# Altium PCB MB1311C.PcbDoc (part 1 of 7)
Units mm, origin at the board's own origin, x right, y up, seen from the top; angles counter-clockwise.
Board outline 100.03 x 67.03 mm, 6 copper layers (Top Layer, layer2, layer3, layer4, layer5, Bottom Layer), stack 1.208 mm thick; 366 components, 356 nets, 1582 pads, 964 vias.
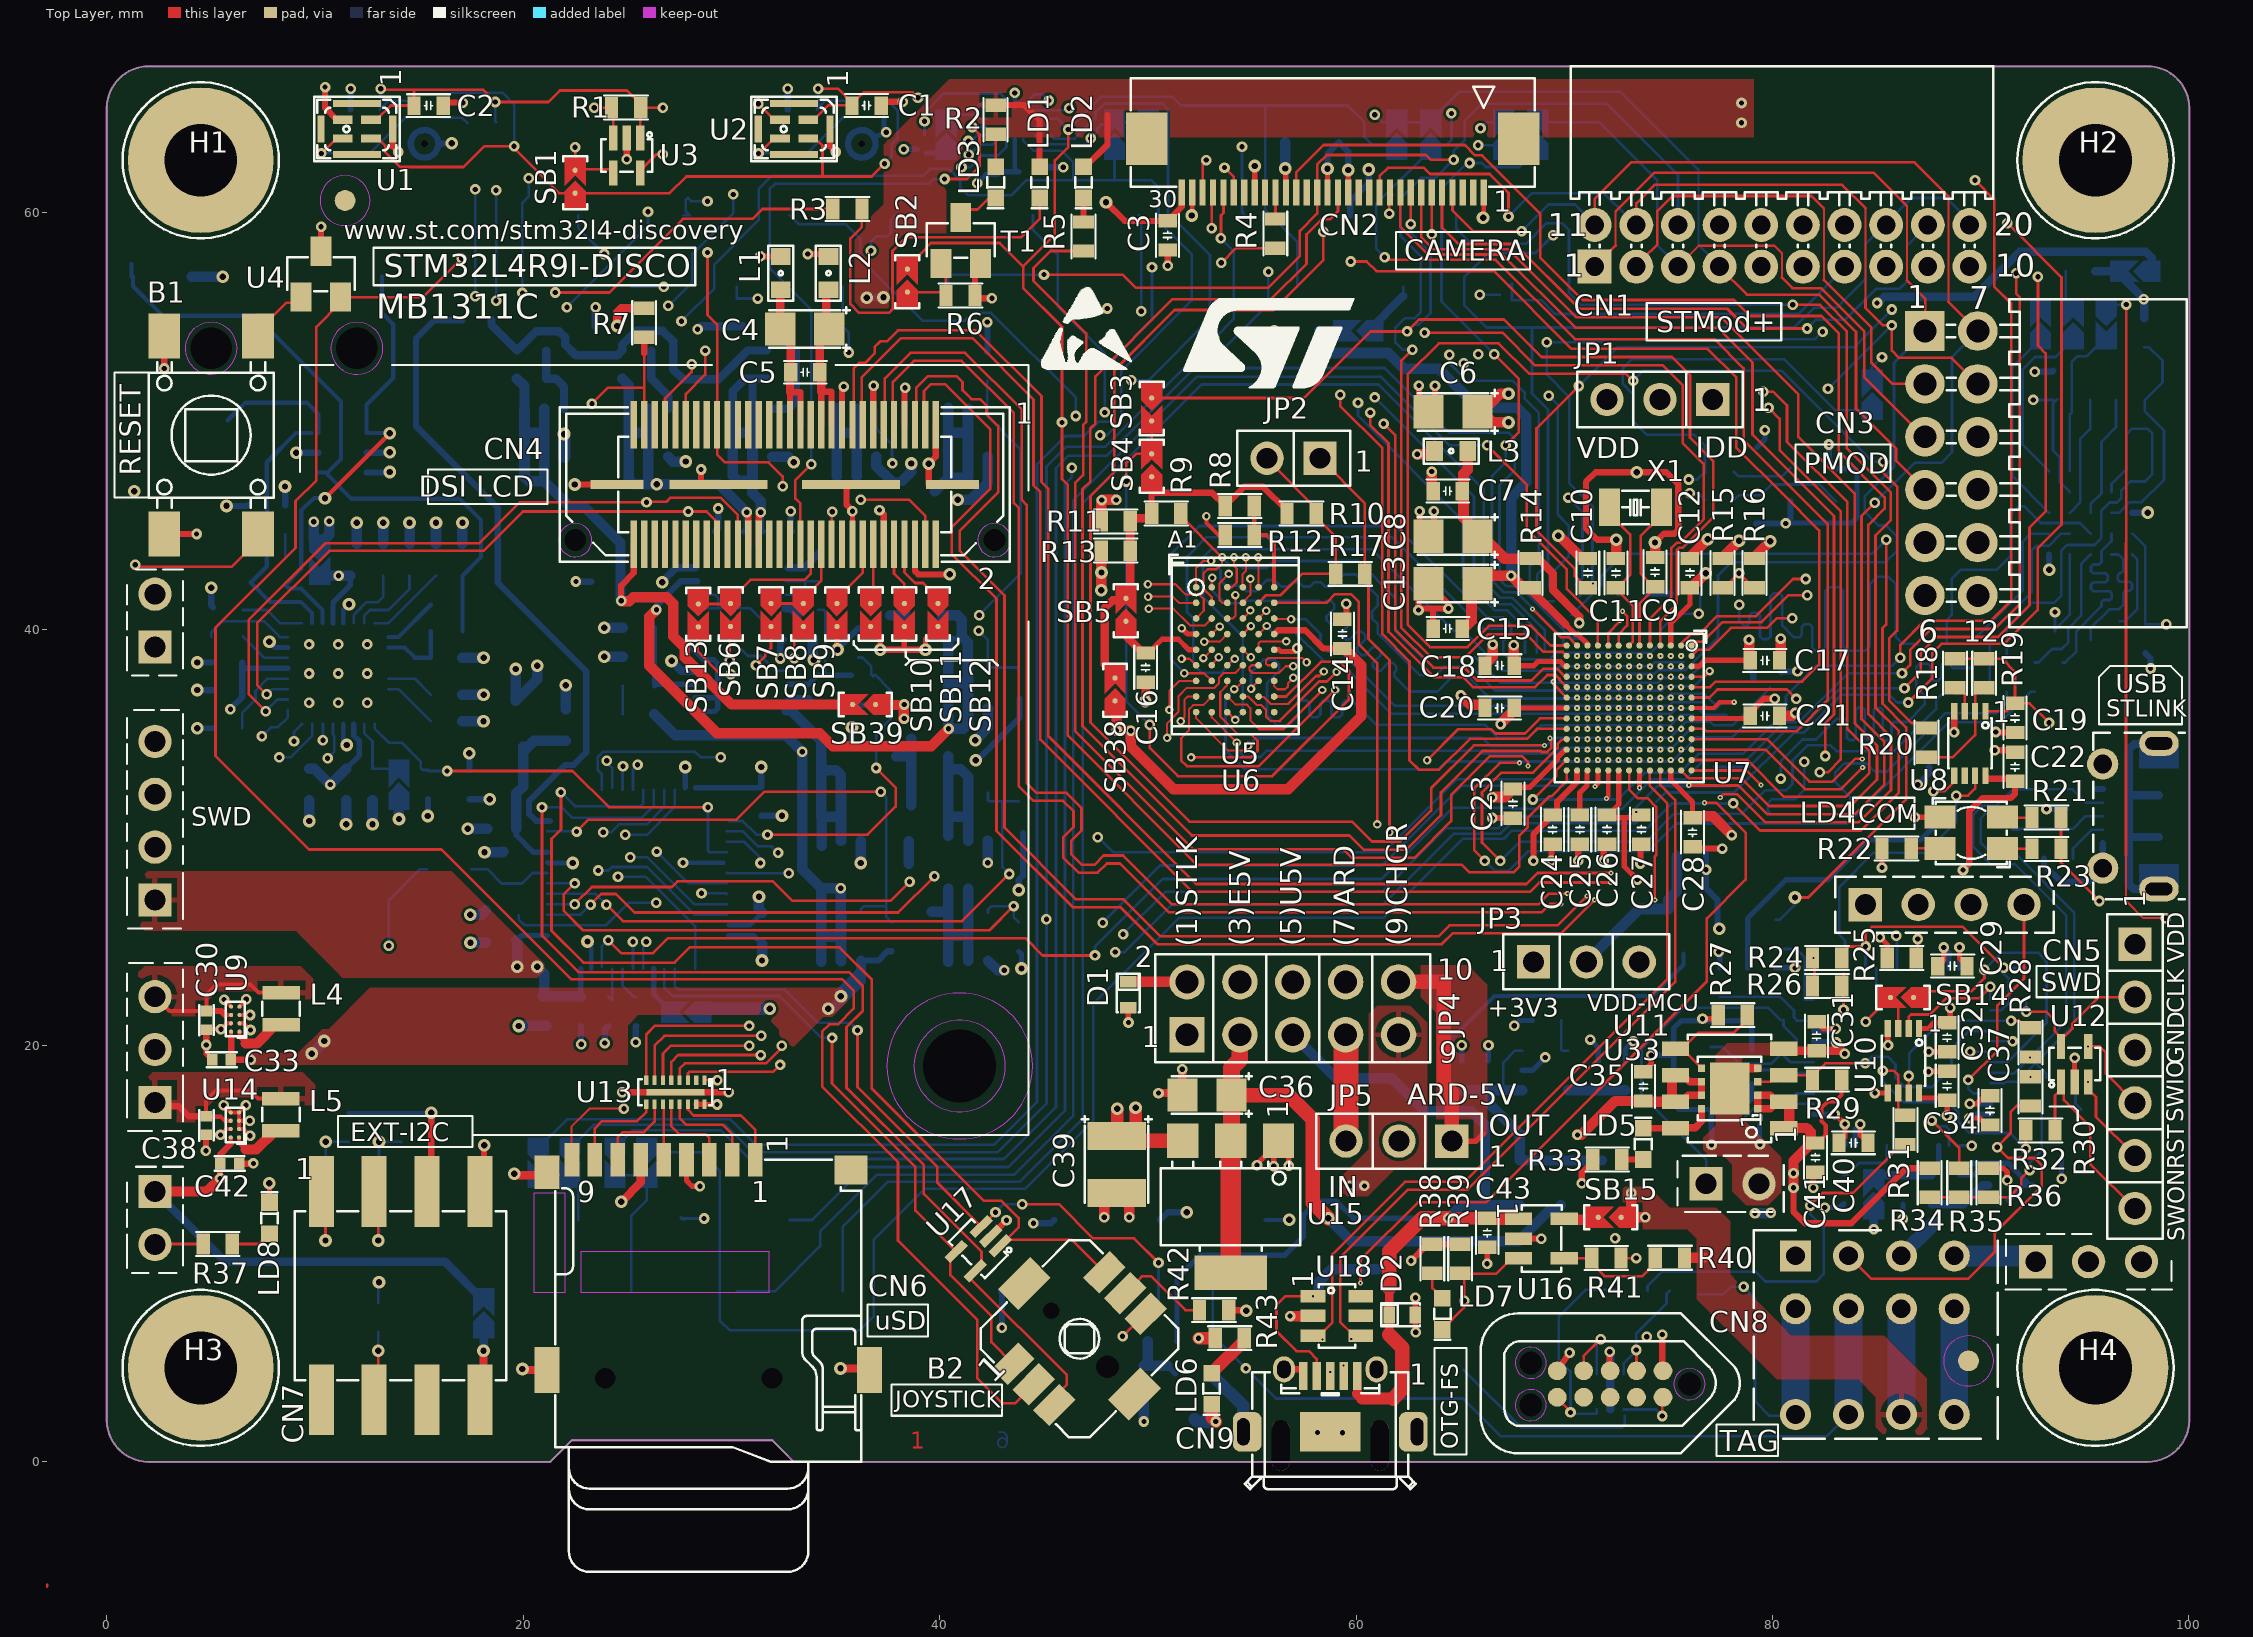
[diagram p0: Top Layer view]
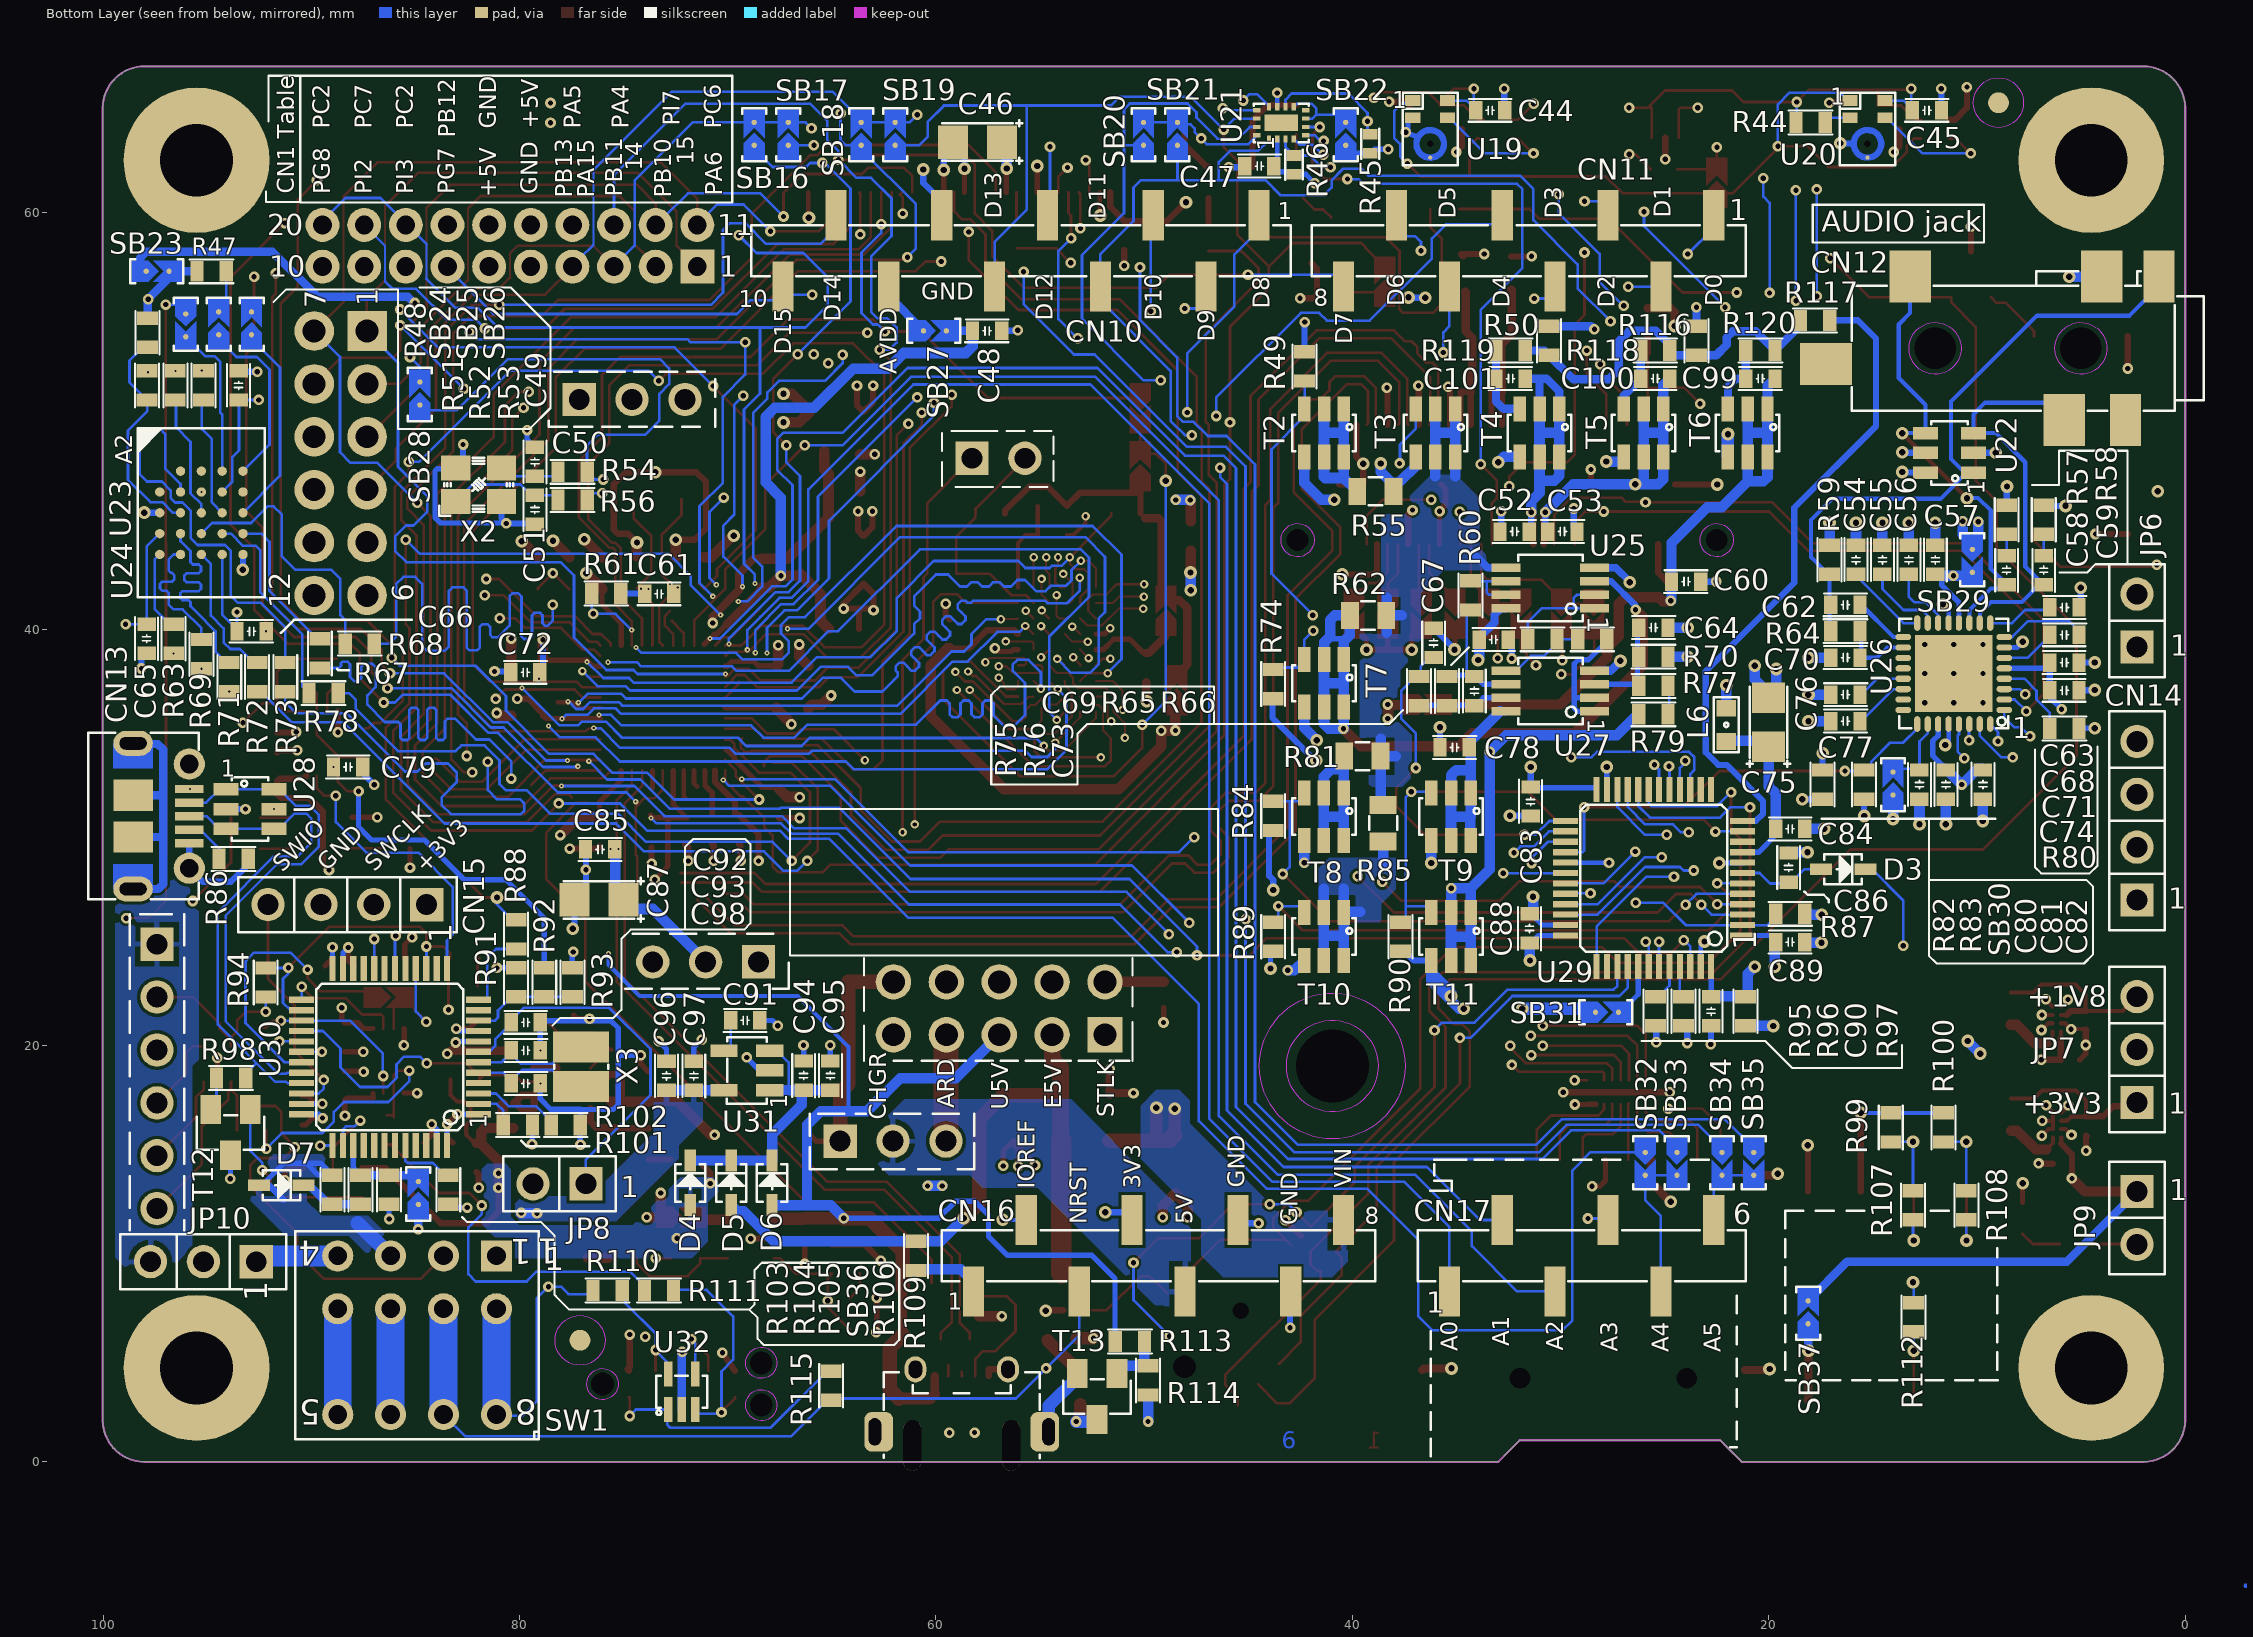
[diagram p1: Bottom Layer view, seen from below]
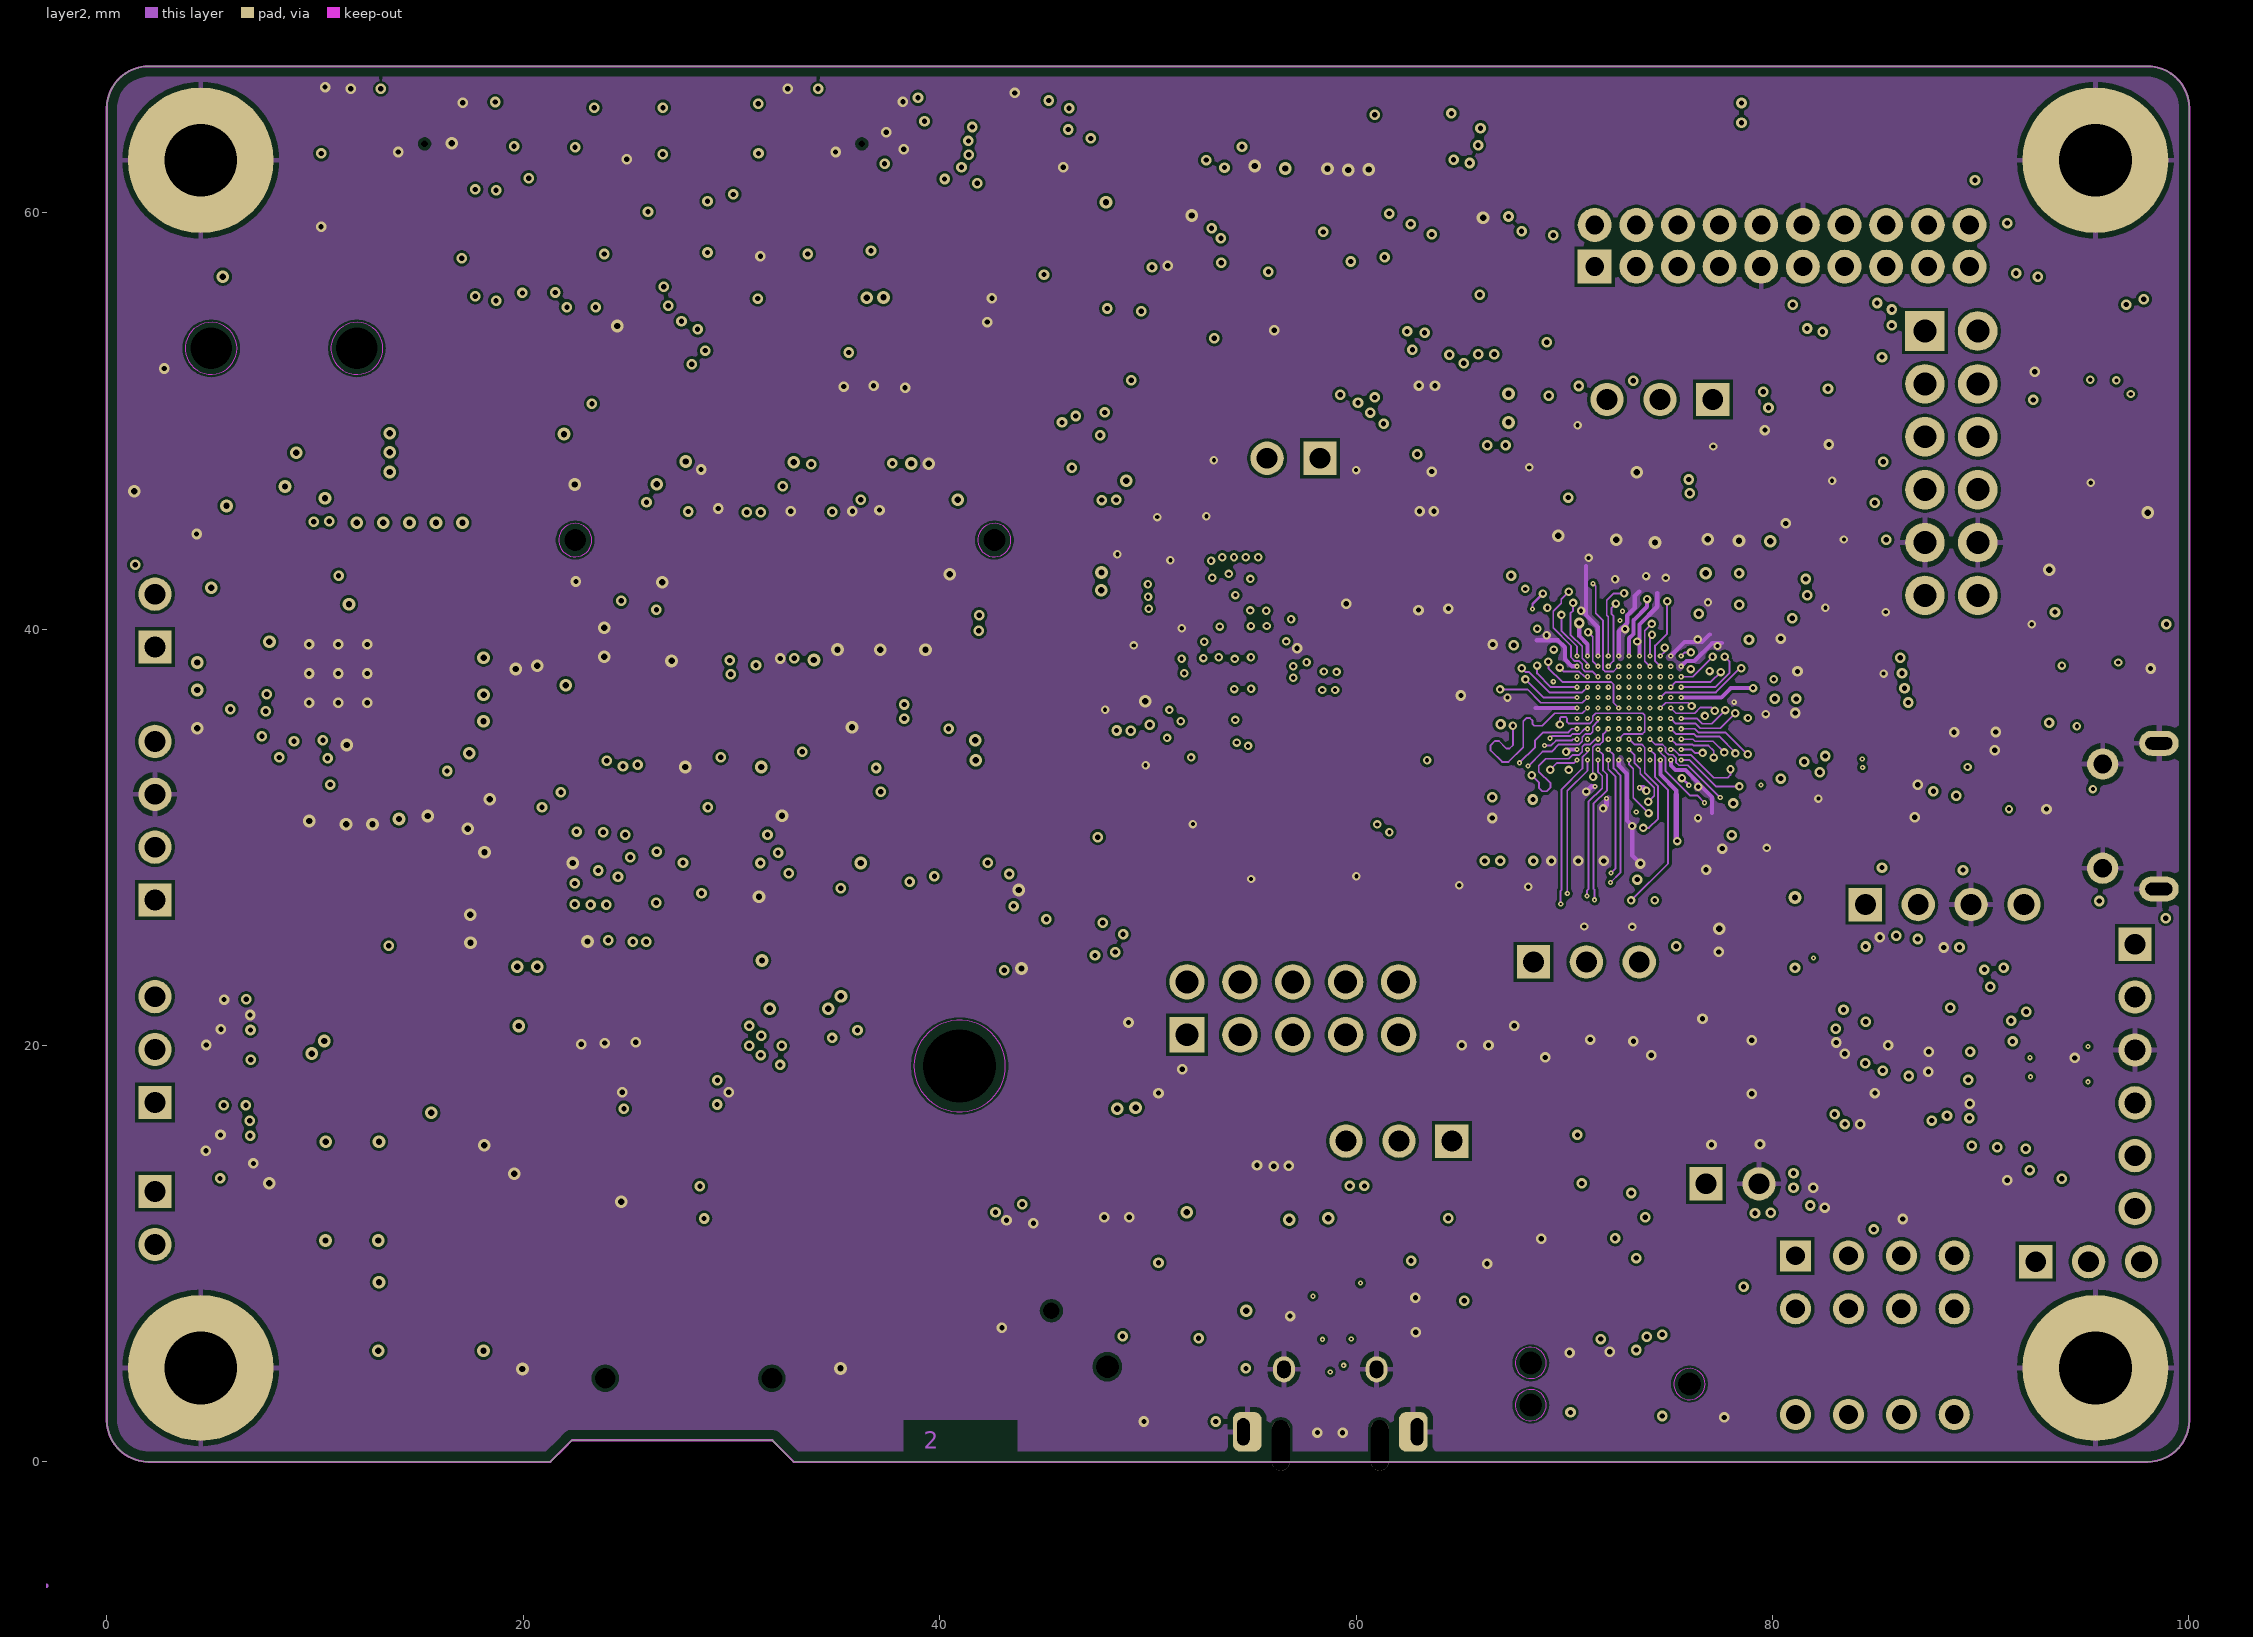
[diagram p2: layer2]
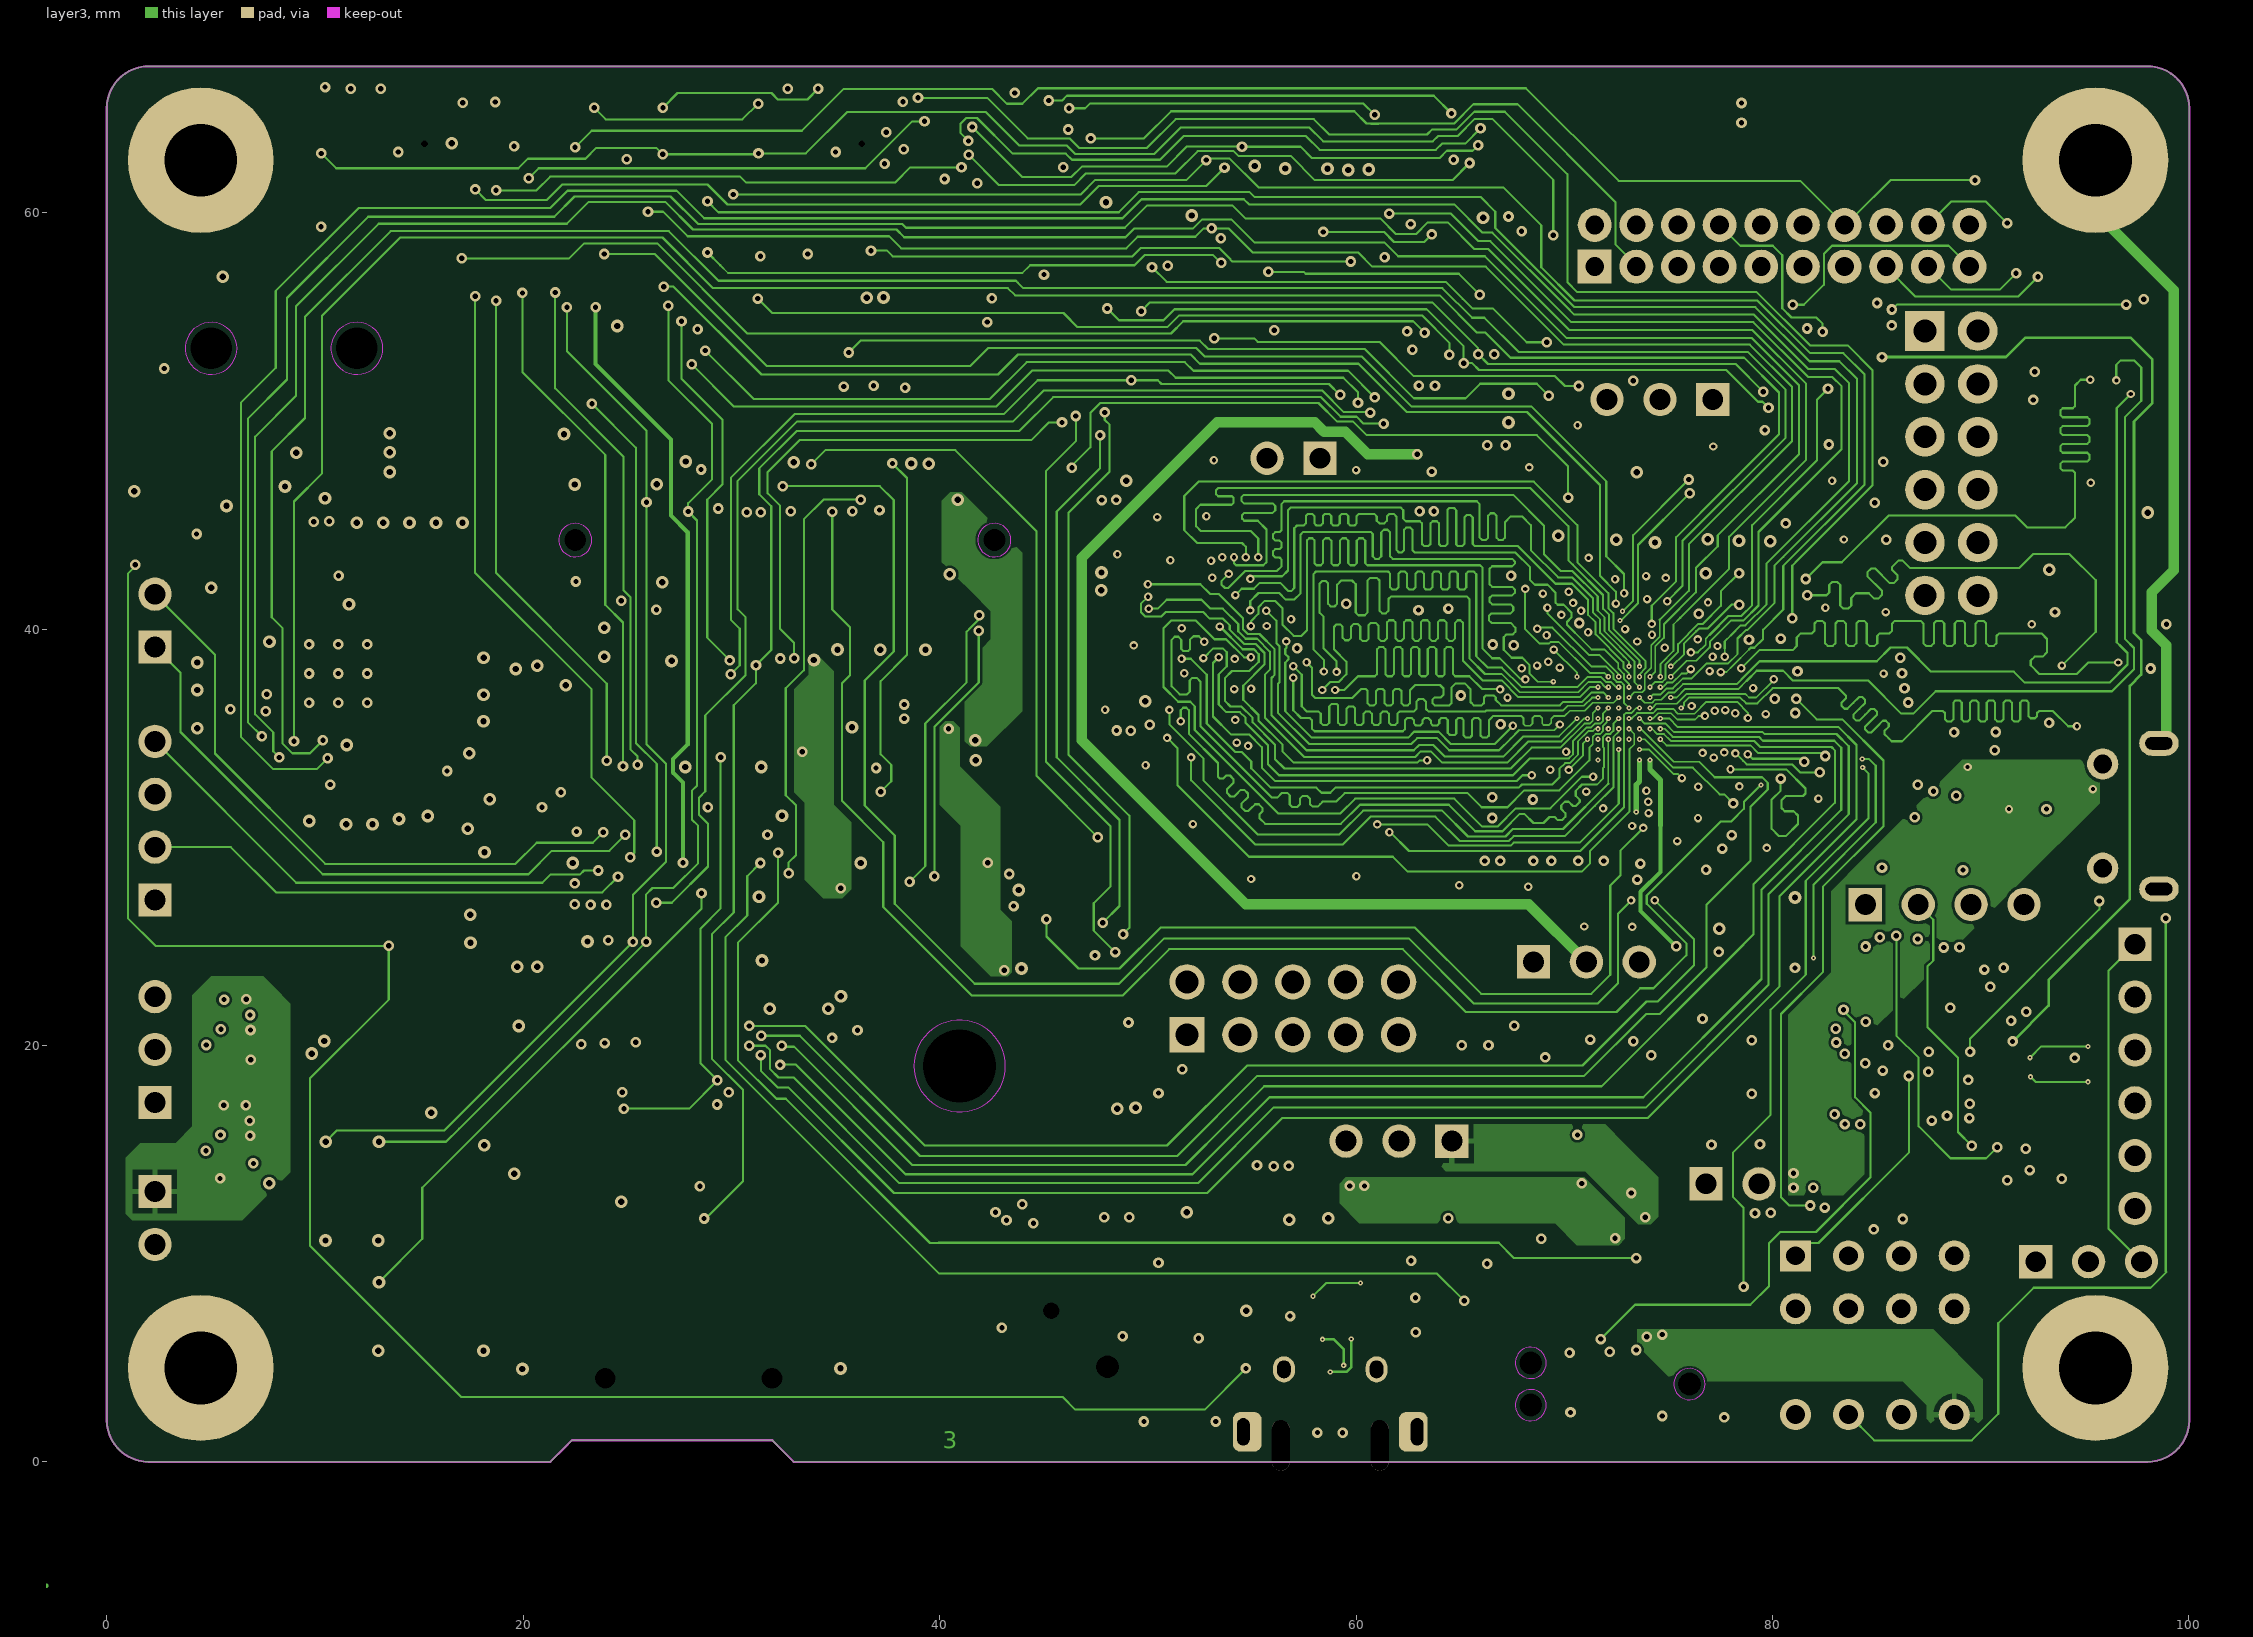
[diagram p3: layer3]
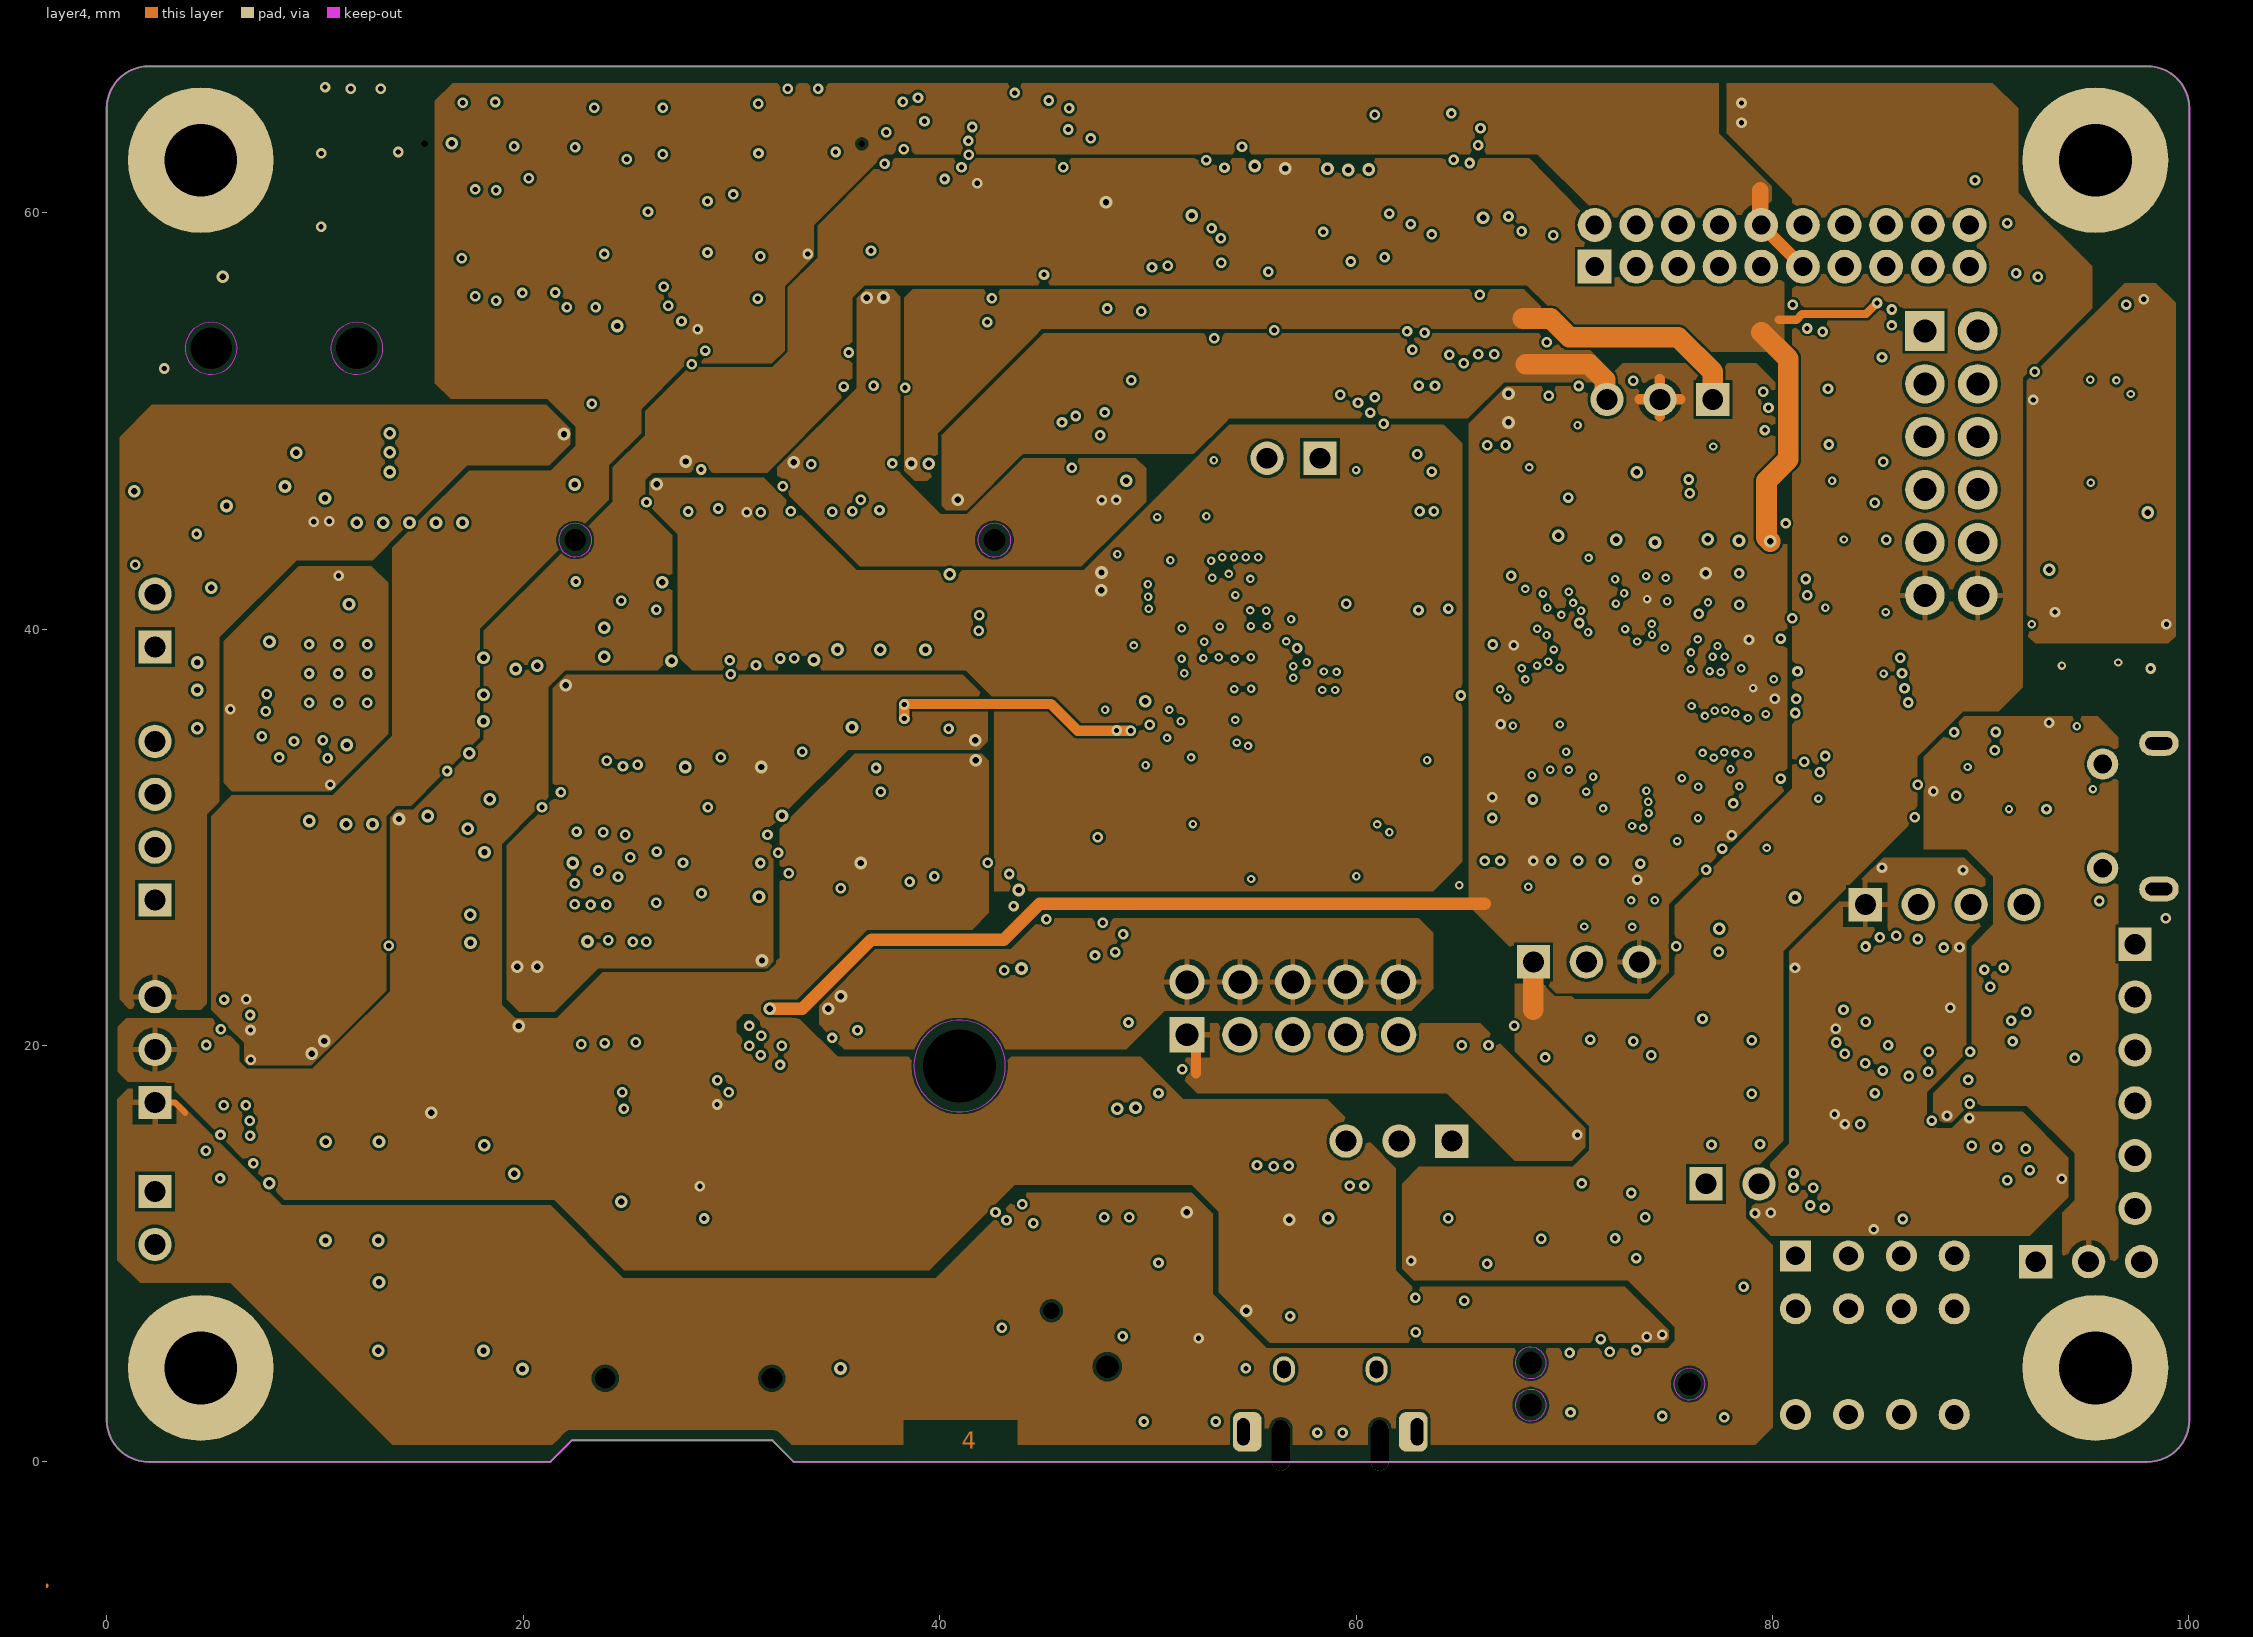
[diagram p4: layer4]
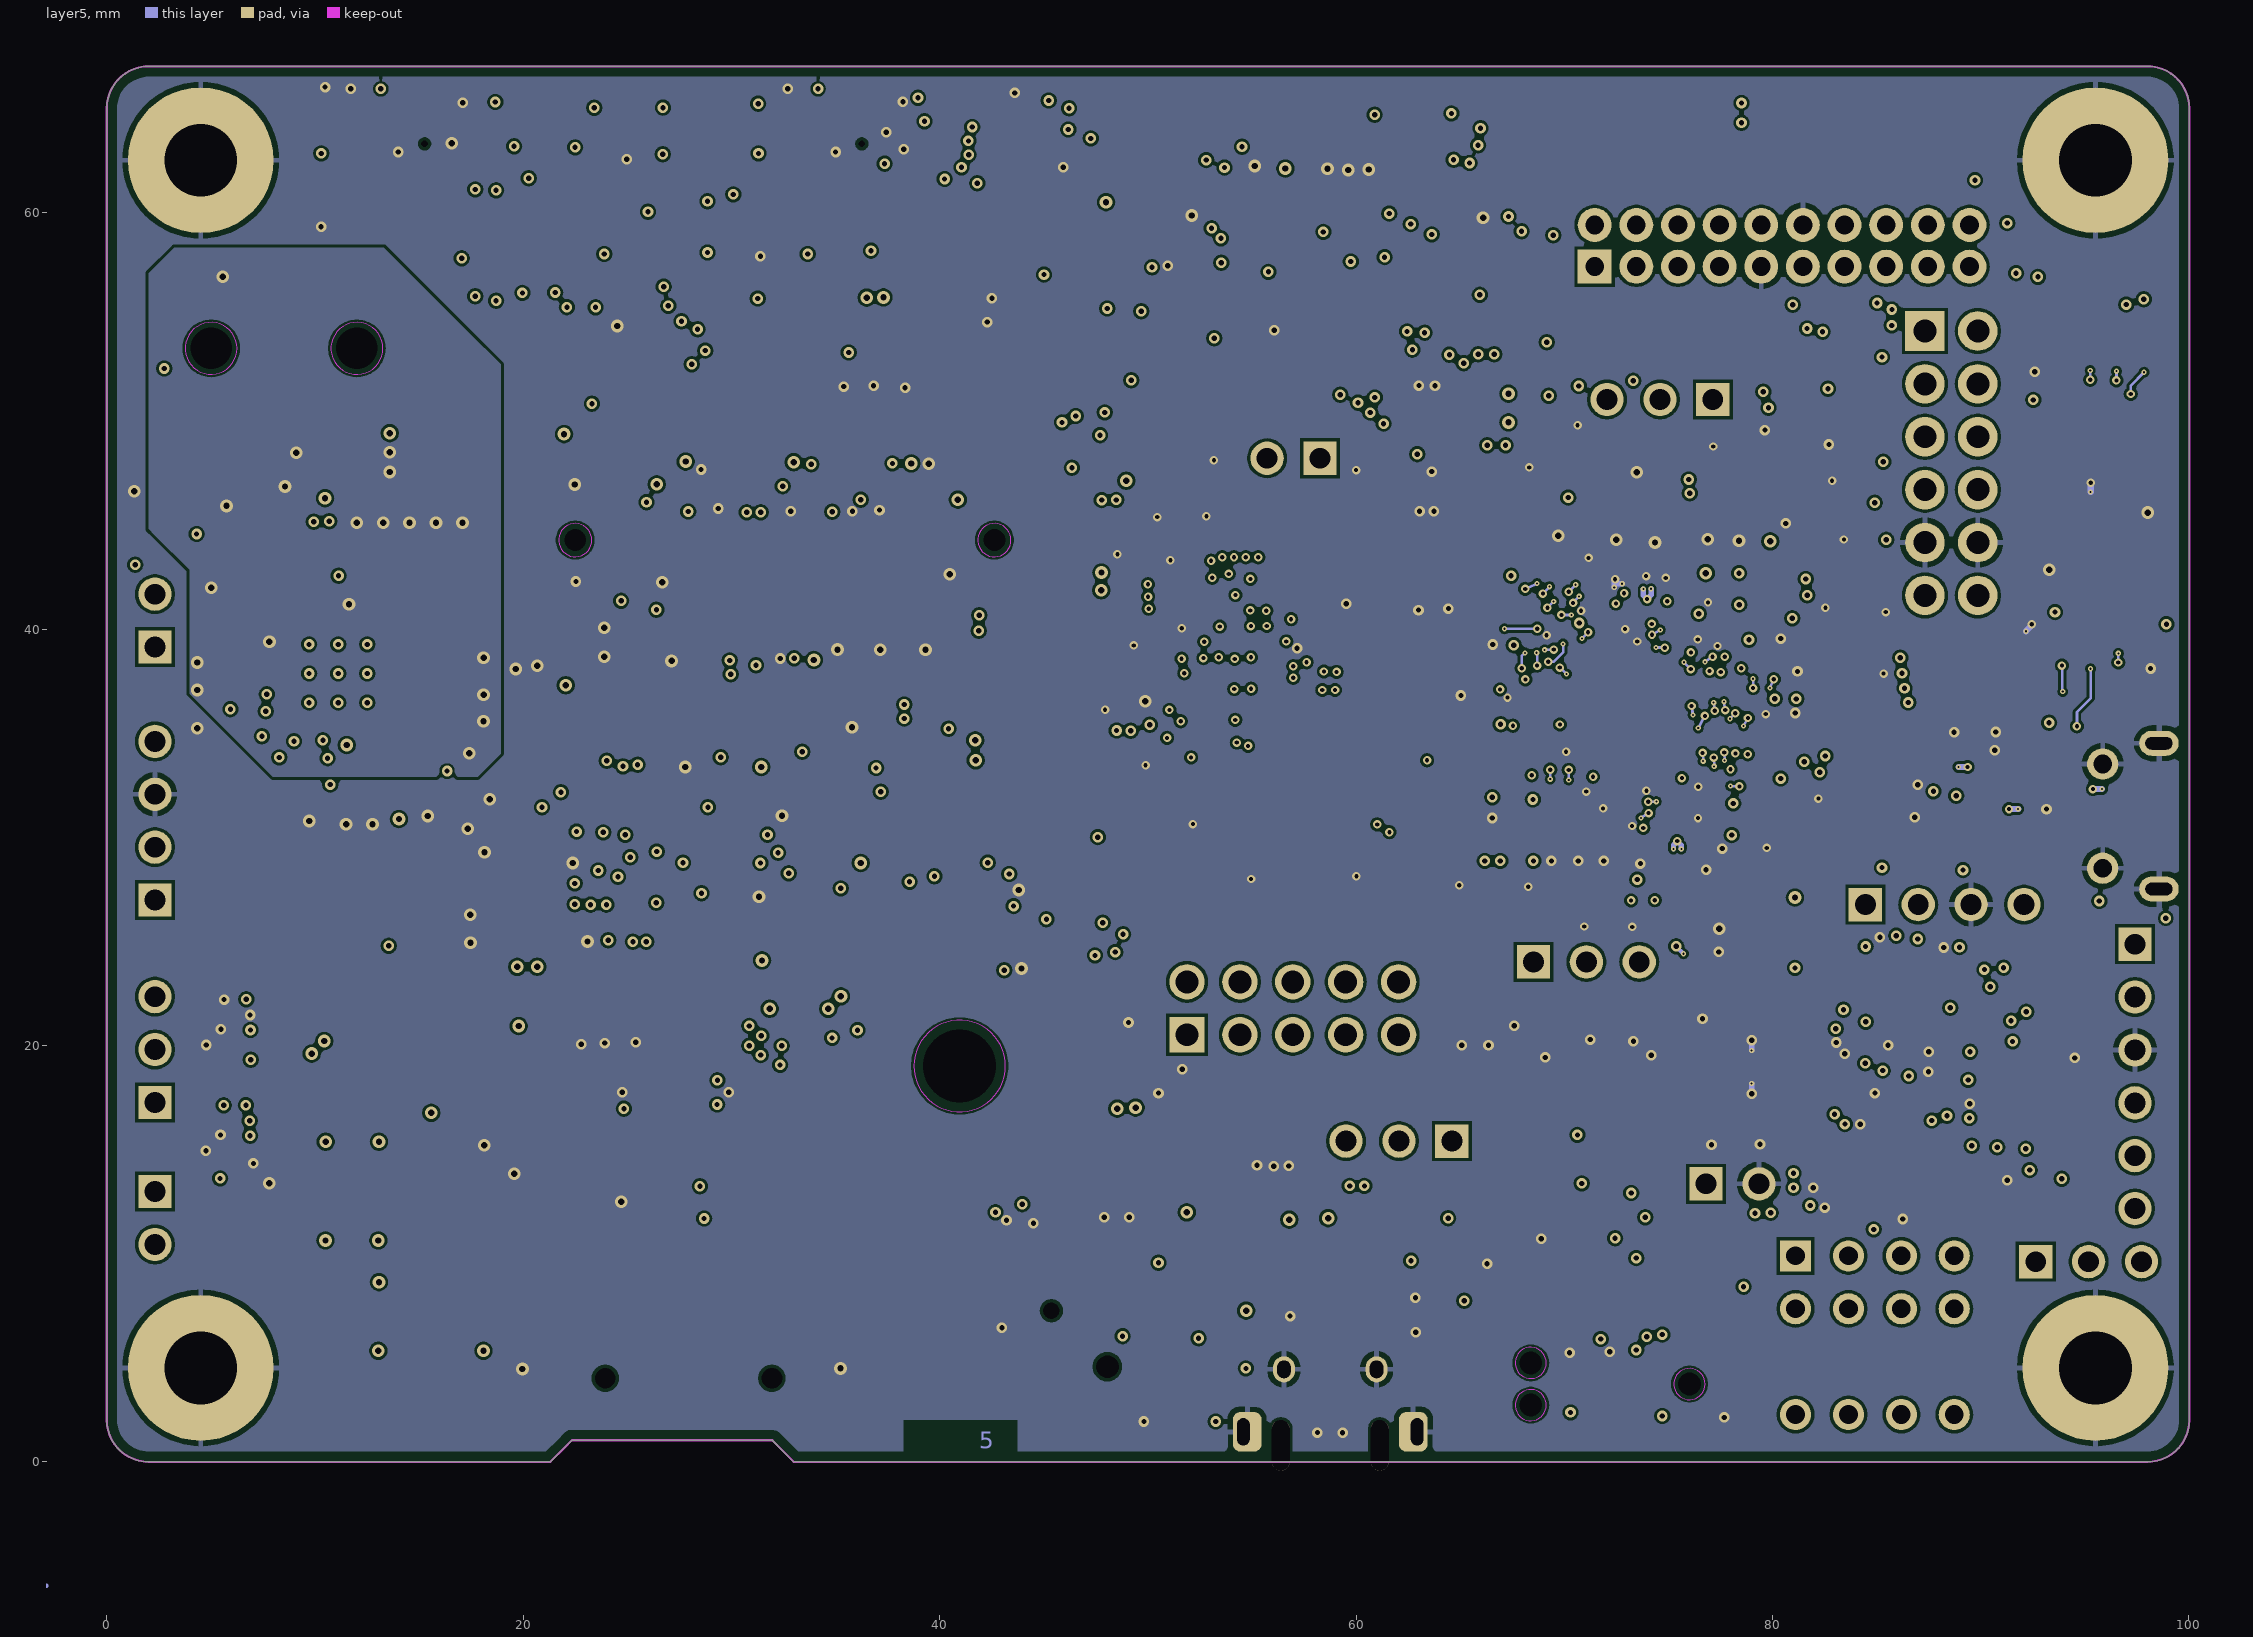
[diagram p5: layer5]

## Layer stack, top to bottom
Top Solder: solder mask 0.01, Solder Resist, Dk 3.5
Top Layer: signal copper 0.042
Dielectric 1: core 0.072, FR-4, Dk 4.2
layer2: signal copper 0.035
Dielectric 2: prepreg 0.0785, FR-4, Dk 4.3
layer3: signal copper 0.0175
Dielectric 3: core 0.71, FR-4, Dk 4.3
layer4: signal copper 0.0175
Dielectric 4: prepreg 0.087, FR-4, Dk 4.3
layer5: signal copper 0.035
Dielectric 5: core 0.072, FR-4, Dk 4.2
Bottom Layer: signal copper 0.042
Bottom Solder: solder mask 0.01, Solder Resist, Dk 3.5

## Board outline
2.013,0 21.3,0 22.013,0.713 22.338,1.038 31.963,1.038 32.988,0 33.263,0 95.676,0 98.013,0 ccw(c98.013,2.013) 100.026,2.013 100.026,65.013 ccw(c98.013,65.013) 98.013,67.026 2.013,67.026 ccw(c2.013,65.013) 0,65.013 0,2.013 ccw(c2.013,2.013)

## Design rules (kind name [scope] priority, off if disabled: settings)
AssemblyTestPointUsage AssemblyTestPointUsage_1 [All] p1:
AssemblyTestPointUsage [All] p2:
AssemblyTestpoint AssemblyTestpoint_1 [All] p1: testpointundercomponent=TRUE minsize=1.016 maxsize=2.54 preferedsize=1.524 minholesize=0 maxholesize=1.016 preferedholesize=0.813 testpointgrid=0.025 usegrid=TRUE gridtolerance=0 allowsidetop=TRUE allowsidebottom=TRUE
AssemblyTestpoint [All] p2: testpointundercomponent=TRUE minsize=1.016 maxsize=2.54 preferedsize=1.524 minholesize=0 maxholesize=1.016 preferedholesize=0.813 testpointgrid=0.025 usegrid=TRUE gridtolerance=0 allowsidetop=TRUE allowsidebottom=TRUE
BoardOutlineClearance [All] p1: gap=0.5 ignorepadtopadclearanceinfootprint=FALSE
Clearance [All] p1: gap=0.127 ignorepadtopadclearanceinfootprint=FALSE except(0: Arc-Region Arc-Hole Track-Region Track-Hole SMDPad-Region SMDPad-Hole THPad-Region THPad-Hole Via-Region Via-Hole Fill-Region Fill-Hole Poly-Region Poly-Hole Region-Region Region-Hole Text-Hole; 0.078: Track-Via; 0.09: Track-Track; 0.12: Arc-Arc Arc-Track Arc-SMDPad Arc-THPad Arc-Via Arc-Poly Track-SMDPad Track-THPad SMDPad-SMDPad SMDPad-THPad SMDPad-Via THPad-Via; 0.15: THPad-Poly Fill-Poly Poly-Poly)
ComponentClearance ComponentClearance_DI [InComponent('U11') vs InComponent('U33')] p1: gap=-10 collisioncheckmode=3 verticalgap=-10 showdistances=TRUE
ComponentClearance ComponentClearance_1 [All] p2: gap=0.254 collisioncheckmode=3 verticalgap=0.254 showdistances=FALSE
ComponentClearance [All] p3: gap=0.025 collisioncheckmode=3 verticalgap=2540 showdistances=FALSE
DiffPairsRouting PAIR__DSI [InDifferentialPairClass('DSI')] p1: maxlimit=0.254 minlimit=0.15 mostfreqgap=0.254 toplayer_minwidth=0.088 toplayer_maxwidth=0.127 toplayer_prefwidth=0.127 midlayer1_prefgap=0.15 midlayer1_minwidth=0.088 midlayer1_maxwidth=0.127 midlayer1_prefwidth=0.088 midlayer2_minwidth=0.088 midlayer2_maxwidth=0.127 midlayer2_prefwidth=0.127 midlayer3_minwidth=0.088 midlayer3_maxwidth=0.127 midlayer3_prefwidth=0.127 midlayer4_minwidth=0.088 midlayer4_maxwidth=0.127 midlayer4_prefwidth=0.127 bottomlayer_minwidth=0.088 bottomlayer_maxwidth=0.127 bottomlayer_prefwidth=0.127 maxuncoupledlength=12.7
DiffPairsRouting PAIR__USB [InDifferentialPairClass('USB')] p2: maxlimit=0.254 minlimit=0.254 mostfreqgap=0.254 toplayer_minwidth=0.122 toplayer_maxwidth=0.122 toplayer_prefwidth=0.122 midlayer1_minwidth=0.122 midlayer1_maxwidth=0.122 midlayer1_prefwidth=0.122 midlayer2_minwidth=0.122 midlayer2_maxwidth=0.122 midlayer2_prefwidth=0.122 midlayer3_minwidth=0.122 midlayer3_maxwidth=0.122 midlayer3_prefwidth=0.122 midlayer4_minwidth=0.122 midlayer4_maxwidth=0.122 midlayer4_prefwidth=0.122 bottomlayer_minwidth=0.122 bottomlayer_maxwidth=0.122 bottomlayer_prefwidth=0.122 maxuncoupledlength=12.7
FabricationTestPointUsage FabricationTestPointUsage_1 [All] p1: valid=0 allowmultiple=FALSE
FabricationTestPointUsage [All] p2: valid=0 allowmultiple=FALSE
FabricationTestpoint FabricationTestpoint_1 [All] p1: side=3 testpointundercomponent=TRUE minsize=1.016 maxsize=2.54 preferedsize=1.524 minholesize=0 maxholesize=1.016 preferedholesize=0.813 testpointgrid=0.025 allowsidetop=TRUE allowsidebottom=TRUE usegrid=TRUE gridtolerance=0
FabricationTestpoint [All] p2: side=3 testpointundercomponent=TRUE minsize=1.016 maxsize=2.54 preferedsize=1.524 minholesize=0 maxholesize=1.016 preferedholesize=0.813 testpointgrid=0.025 allowsidetop=TRUE allowsidebottom=TRUE usegrid=TRUE gridtolerance=0
FanoutControl Fanout_Default_1 [All] p1: bgadir=Out bgaviamode=Centered fanoutstyle=Auto fanoutdirection=Alternating viagrid=0.025 // Fanout_Default (Default Rule)
FanoutControl Fanout_Small_1 [(CompPinCount < 5)] p2: bgadir=Out bgaviamode=Centered fanoutstyle=Auto fanoutdirection=OutThenIn viagrid=0.025 // Fanout_Small (Default Rule)
FanoutControl Fanout_SOIC_1 [IsSOIC] p3: bgadir=Out bgaviamode=Centered fanoutstyle=Auto fanoutdirection=Alternating viagrid=0.025 // Fanout_SOIC (Default Rule)
FanoutControl Fanout_LCC_1 [IsLCC] p4: bgadir=Out bgaviamode=Centered fanoutstyle=Auto fanoutdirection=Alternating viagrid=0.025 // Fanout_LCC (Default Rule)
FanoutControl Fanout_BGA_1 [IsBGA] p5: bgadir=Out bgaviamode=Centered fanoutstyle=Auto fanoutdirection=Alternating viagrid=0.025 // Fanout_BGA (Default Rule)
FanoutControl Fanout_BGA [IsBGA] p6: bgadir=Out bgaviamode=Centered fanoutstyle=Auto fanoutdirection=Alternating viagrid=0.025 // Fanout_BGA (Default Rule)
FanoutControl Fanout_LCC [IsLCC] p7: bgadir=Out bgaviamode=Centered fanoutstyle=Auto fanoutdirection=Alternating viagrid=0.025 // Fanout_LCC (Default Rule)
FanoutControl Fanout_SOIC [IsSOIC] p8: bgadir=Out bgaviamode=Centered fanoutstyle=Auto fanoutdirection=Alternating viagrid=0.025 // Fanout_SOIC (Default Rule)
FanoutControl Fanout_Small [(CompPinCount < 5)] p9: bgadir=Out bgaviamode=Centered fanoutstyle=Auto fanoutdirection=OutThenIn viagrid=0.025 // Fanout_Small (Default Rule)
FanoutControl Fanout_Default [All] p10: bgadir=Out bgaviamode=Centered fanoutstyle=Auto fanoutdirection=Alternating viagrid=0.025 // Fanout_Default (Default Rule)
Height Height_1 [All] p1: minheight=0 maxheight=25.4 prefheight=12.7
Height [All] p2: minheight=0 maxheight=25.4 prefheight=12.7
HoleSize HoleSize_1 [All] p1: absolutevalues=TRUE maxlimit=2.54 minlimit=0.025 maxpercent=80.000 minpercent=20.000
HoleSize [All] p2: absolutevalues=TRUE maxlimit=10 minlimit=0.15 maxpercent=80.000 minpercent=20.000
HoleToHoleClearance HoleToHoleClearance_1 [All] p1: gap=0.254 allowstackedmicrovias=TRUE
HoleToHoleClearance [All] p2: gap=0.254 allowstackedmicrovias=TRUE
LayerPairs LayerPairs_1 [All] p1: enforce=TRUE
LayerPairs [All] p2: enforce=TRUE
MatchedLengths psram_adr_ctrl [InNetClass('PSRAM_adr_ctrl')] p1: tolerance=5.1 checknetsindiffpair=FALSE checkdiffpairvsdiffpair=TRUE checkxsignals=TRUE checkothers=TRUE
MatchedLengths octospim [InxSignalClass('OCTOSPIM')] p2: tolerance=5.1 checknetsindiffpair=FALSE checkdiffpairvsdiffpair=TRUE checkxsignals=TRUE checkothers=TRUE
MatchedLengths Psram_data [InNetClass('PSRAM_data')] p3: tolerance=5.1 checknetsindiffpair=FALSE checkdiffpairvsdiffpair=TRUE checkxsignals=TRUE checkothers=TRUE
MinimumSolderMaskSliver MinimumSolderMaskSliver_1 [All] p1: minsoldermaskwidth=0.254
MinimumSolderMaskSliver [All] p2: minsoldermaskwidth=0.254
NetAntennae NetAntennae_1 [All] p1: netantennaetolerance=0
NetAntennae [All] p2: netantennaetolerance=0
PasteMaskExpansion PasteMaskExpansion_1 [All] p1: expansion=0
PasteMaskExpansion [All] p2: expansion=0
PermittedLayers [All] p1: toplayerpermitted=TRUE bottomlayerpermitted=TRUE
PlaneClearance PlaneClearance_1 [All] p1: clearance=0.508
PlaneClearance [All] p2: clearance=0.508
PlaneConnect PlaneConnect_1 [All] p1: planeconnectstyle=Direct reliefexpansion=0.508 reliefentries=4 reliefconductorwidth=0.254 reliefairgap=0.254
PlaneConnect [All] p2: planeconnectstyle=Relief reliefexpansion=0.508 reliefentries=4 reliefconductorwidth=0.254 reliefairgap=0.254
PolygonConnect PolygonConnect_6 [All vs IsNamedPolygon('GND_L01_P780')] p1: connectstyle=Direct reliefconductorwidth=0.254 reliefentries=4 polygonreliefangle="90 Angle" airgapwidth=0.254
PolygonConnect PolygonConnect_5 [All vs IsNamedPolygon('GND_L01_P780')] p2: thpad.connectstyle=Relief thpad.reliefconductorwidth=0.35 thpad.reliefentries=4 thpad.polygonreliefangle="90 Angle" thpad.airgapwidth=0.3 smdpad.connectstyle=Direct smdpad.reliefconductorwidth=0.254 smdpad.reliefentries=4 smdpad.polygonreliefangle="90 Angle" smdpad.airgapwidth=0.254 via.connectstyle=Direct via.reliefconductorwidth=0.254 via.reliefentries=4 via.polygonreliefangle="90 Angle" via.airgapwidth=0.254
PolygonConnect PolygonConnect_4 [All vs IsVia] p3: connectstyle=Direct reliefconductorwidth=0.254 reliefentries=4 polygonreliefangle="90 Angle" airgapwidth=0.254
PolygonConnect PolygonConnect_3 [All vs IsPad] p4: connectstyle=Relief reliefconductorwidth=0.254 reliefentries=4 polygonreliefangle="90 Angle" airgapwidth=0.254
PolygonConnect PolygonConnect_2 [All] p5: connectstyle=Relief reliefconductorwidth=0.254 reliefentries=4 polygonreliefangle="90 Angle" airgapwidth=0.254
PolygonConnect PolygonConnect_VIAS-DIRECT [(ObjectKind = 'Via')] p6: connectstyle=Direct reliefconductorwidth=0.254 reliefentries=4 polygonreliefangle="90 Angle" airgapwidth=0.254
PolygonConnect PolygonConnect_1 [All] p7: connectstyle=Direct reliefconductorwidth=0.254 reliefentries=4 polygonreliefangle="90 Angle" airgapwidth=0.254
PolygonConnect 4_PTH_MECA [(ObjectKind = 'Pad') And (AsMM(HoleDiameter) = 3.5)] p8: connectstyle=Direct reliefconductorwidth=0.254 reliefentries=4 polygonreliefangle="90 Angle" airgapwidth=0.254
PolygonConnect PAD_CMS_NC [(ObjectKind = 'Pad') And (AsMM(HoleDiameter) = 0)] p9: connectstyle=NoConnect reliefconductorwidth=0.254 reliefentries=4 polygonreliefangle="90 Angle" airgapwidth=0.254
PolygonConnect VIAS_DIRECT [(ObjectKind = 'Via')] p10: connectstyle=Direct reliefconductorwidth=0.254 reliefentries=4 polygonreliefangle="90 Angle" airgapwidth=0.254
PolygonConnect [All] p11: connectstyle=Relief reliefconductorwidth=0.3 reliefentries=4 polygonreliefangle="90 Angle" airgapwidth=0.3
RoutingCorners RoutingCorners_1 [All] p1: cornerstyle=45-Degree minsetback=2.54 maxsetback=2.54
RoutingCorners [All] p2: cornerstyle=45-Degree minsetback=2.54 maxsetback=2.54
RoutingTopology RoutingTopology_1 [All] p1: topology=Shortest
RoutingTopology [All] p2: topology=Shortest
RoutingVias thru [InDrillLayerPair('Top Layer - Bottom Layer')] p1: holewidth=0.254 width=0.508 viastyle="Through Hole" minholewidth=0.102 minwidth=0.254 maxholewidth=0.305 maxwidth=0.61 useviatemplates=TRUE viatemplateguid#1={340DC7B5-3F1E-47EE-990D-81B2755D6B04} viatemplateguid#2={247BE16E-88AE-4C41-9598-B4796CDE4816} viatemplateguid#3={E3B873A7-E7F3-4F44-A42C-17ADC36A370E} viatemplatename#1=v41h20m0mx0 viatemplatename#2=v51h25m0mx0 viatemplatename#3=v61h30m0mx0
RoutingVias buried [InDrillLayerPair('layer2 - layer5')] p2: holewidth=0.254 width=0.508 viastyle="Through Hole" minholewidth=0.102 minwidth=0.254 maxholewidth=0.305 maxwidth=0.61 useviatemplates=TRUE viatemplateguid#1={340DC7B5-3F1E-47EE-990D-81B2755D6B04} viatemplateguid#2={247BE16E-88AE-4C41-9598-B4796CDE4816} viatemplatename#1=v41h20m0mx0 viatemplatename#2=v51h25m0mx0
RoutingVias laser12 [InDrillLayerPair('Top Layer - layer2')] p3: holewidth=0.254 width=0.508 viastyle="Through Hole" minholewidth=0.102 minwidth=0.254 maxholewidth=0.305 maxwidth=0.61 useviatemplates=TRUE viatemplateguid#1={9272D162-69AC-415E-8B8A-D644504FA463} viatemplatename#1=v25h10m0
RoutingVias laser23 [InDrillLayerPair('layer2 - layer3')] p4: holewidth=0.254 width=0.508 viastyle="Through Hole" minholewidth=0.102 minwidth=0.254 maxholewidth=0.305 maxwidth=0.61 useviatemplates=TRUE viatemplateguid#1={340DC7B5-3F1E-47EE-990D-81B2755D6B04} viatemplatename#1=v41h20m0mx0
RoutingVias laser13 [InDrillLayerPair('Top Layer - layer3')] p5: holewidth=0.254 width=0.508 viastyle="Through Hole" minholewidth=0.102 minwidth=0.254 maxholewidth=0.305 maxwidth=0.61 useviatemplates=TRUE viatemplateguid#1={9272D162-69AC-415E-8B8A-D644504FA463} viatemplatename#1=v25h10m0
RoutingVias laser56 [InDrillLayerPair('layer5 - Bottom Layer')] p6: holewidth=0.254 width=0.508 viastyle="Through Hole" minholewidth=0.102 minwidth=0.254 maxholewidth=0.305 maxwidth=0.61 useviatemplates=TRUE viatemplateguid#1={323C149F-07D9-473E-B805-4447FED07B1E} viatemplatename#1=v25h10mx0
SilkToBoardRegionClearance SilkToBoardRegionClearance_1 [All] p1:
SilkToBoardRegionClearance [All] p2:
SilkToSilkClearance SilkToSilkClearance_1 [All] p1: silktosilkclearance=0.254
SilkToSilkClearance [All] p2: silktosilkclearance=0.1
SilkToSolderMaskClearance SilkToSolderMaskClearance_1 [IsPad] p1: minsilkscreentomaskgap=0.254 clearancetoexposedcopper=TRUE
SilkToSolderMaskClearance [IsPad] p2: minsilkscreentomaskgap=0.254 clearancetoexposedcopper=TRUE
SolderMaskExpansion SolderMaskExpansion_2 [All] p1: expansion=0.102
SolderMaskExpansion SolderMaskExpansion_1 [Not All] p2: expansion=0.102
SolderMaskExpansion [All] p3: expansion=0.102
UnRoutedNet UnRoutedNet_1 [All] p1:
UnRoutedNet [All] p2:
Width Width_alims [InNetClass('alims')] p1: maxlimit=5 minlimit=0.1 preferedwidth=0.3
Width [All] p2: maxlimit=10 minlimit=0.088 preferedwidth=0.102 toplayer_minwidth=0.102 toplayer_prefwidth=0.127 midlayer3_minwidth=0.102 midlayer4_minwidth=0.102 bottomlayer_minwidth=0.102 bottomlayer_prefwidth=0.127 minimp=50.000000 maximp=50.000000 favimp=50.000000
4 further rules are at their usual default settings.

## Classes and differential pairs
net class alims: 1V8_CODEC 1V8_LCD 3V3_LCD 5V_STL 5V_USB_CHARGER +1V8 +3V3 +3V3_ST_LINK +5V AGND GND
net class PSRAM_data: D0 D1 D2 D3 D4 D5 D6 D7 D8 D9 D10 D11 D12 D13 D14 D15 PSRAM_CLK
net class DCMI_data: DCMI_D0 DCMI_D1 DCMI_D2 DCMI_D3 DCMI_D4 DCMI_D5 DCMI_D6 DCMI_D7
net class PSRAM_adr_ctrl: PSRAM_A0 PSRAM_A1 PSRAM_A2 PSRAM_A3 PSRAM_A4 PSRAM_A5 PSRAM_A6 PSRAM_A7 PSRAM_A8 PSRAM_A9 PSRAM_A10 PSRAM_A11 PSRAM_A12 PSRAM_A13 PSRAM_A14 PSRAM_A15 PSRAM_A16 PSRAM_A17 PSRAM_A18 PSRAM_A19 PSRAM_ADV PSRAM_NBL0 PSRAM_NBL1 PSRAM_NE1 PSRAM_OE PSRAM_WAIT PSRAM_WE
differential pair class DSI: DSI_CK DSI_D0 DSI_D1
differential pair class USB: D STL_USB_D
differential pair D: +D_P -D_N
differential pair USB: +"" -""
differential pair USB_OTG: +"" -""
differential pair USB_OTG_CON: +"" -""
differential pair USB_CON: +"" -""
differential pair DSI_D1: +DSI_D1_P -DSI_D1_N
differential pair DSI_D0: +DSI_D0_P -DSI_D0_N
differential pair DSI_CK: +DSI_CK_P -DSI_CK_N
differential pair STL_USB_D: +STL_USB_D_P -STL_USB_D_N

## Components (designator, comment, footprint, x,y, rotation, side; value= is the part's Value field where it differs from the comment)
B1 ".designator" SWI_WEALTHMETAL_TD-0341_4P 5.013,49.313 r0 top
B2 ".designator" SWI_XIEJIA_MT-008A_6P 46.713,5.913 r45 top locked
C1 ".designator" C0603 36.493,65.143 r0 top
C2 ".designator" C0603 15.453,65.133 r0 top
C3 ".designator" C0603 50.953,58.903 r270 top
C4 ".designator" CPOL_TAJ-A_1206_H180 33.523,54.413 r180 top
C5 ".designator" C0603 33.543,52.333 r180 top
C6 ".designator" CPOL_TAJ-A_1206_H180 64.656,50.432 r180 top
C7 ".designator" C0603 64.402,46.622 r180 top
C8 ".designator" CPOL_TAJ-A_1206_H180 64.656,44.463 r180 top
C9 ".designator" C0603 74.361,42.736 r270 top
C10 ".designator" C0603 71.133,42.685 r90 top
C11 ".designator" C0603 72.482,42.685 r270 top
C12 ".designator" C0603 76.038,42.685 r90 top
C13 ".designator" CPOL_TAJ-A_1206_H180 64.656,42.177 r180 top
C14 ".designator" C0603 59.349,39.766 r90 top
C15 ".designator" C0603 64.402,40.018 r180 top
C16 ".designator" C0603 49.9,38.15 r270 top
C17 ".designator" C0603 79.642,38.494 r0 top
C18 ".designator" C0603 66.894,38.24 r180 top
C19 ".designator" C0603 91.653,35.733 r270 top
C20 ".designator" C0603 66.894,36.208 r180 top
C21 ".designator" C0603 79.642,35.827 r0 top
C22 ".designator" C0603 91.653,33.383 r270 top
C23 ".designator" C0603 67.532,31.613 r270 top
C24 ".designator" C0603 69.444,30.366 r270 top
C25 ".designator" C0603 70.749,30.366 r90 top
C26 ".designator" C0603 72.055,30.366 r270 top
C27 ".designator" C0603 73.706,30.366 r270 top
C28 ".designator" C0603 76.165,30.239 r270 top
C29 ".designator" C0603 88.643,23.813 r180 top
C30 ".designator" C0402 4.783,21.203 r270 top
C31 ".designator" C0603 82.123,20.443 r270 top
C32 ".designator" C0603 88.393,20.393 r90 top
C33 ".designator" C0402 5.513,19.313 r180 top
C34 ".designator" C0603 88.393,18.063 r90 top
C35 ".designator" C0603 73.803,18.033 r270 top
C36 ".designator" CPOL_TAJ-A_1206_H180 52.843,17.623 r180 top
C37 ".designator" C0603 90.453,16.883 r90 top
C38 ".designator" C0402 4.783,16.153 r270 top
C39 ".designator" CPOL_TAJ-B_1210_H210 48.503,14.283 r270 top
C40 ".designator" C0603 83.893,15.323 r0 top
C41 ".designator" C0603 82.063,14.613 r90 top
C42 ".designator" C0402 5.908,14.323 r0 top
C43 ".designator" C0603 66.303,11.003 r270 top
C44 ".designator" C0603 33.383,64.913 r180 bottom
C45 ".designator" C0603 12.403,64.913 r180 bottom
C46 ".designator" CPOL_TAJ-A_1206_H180 58.004,63.386 r0 bottom
C47 ".designator" C0603 44.473,62.233 r0 bottom
C48 ".designator" C0603 57.543,54.323 r180 bottom
C49 ".designator" C0603 93.493,51.703 r90 bottom
C50 ".designator" C0603 79.263,48.033 r90 bottom
C51 ".designator" C0603 79.263,45.733 r270 bottom
C52 ".designator" C0603 32.213,44.683 r180 bottom
C53 ".designator" C0603 29.913,44.683 r0 bottom
C54 ".designator" C0603 15.812,43.324 r270 bottom
C55 ".designator" C0603 14.542,43.324 r270 bottom
C56 ".designator" C0603 13.272,43.324 r270 bottom
C57 ".designator" C0603 12.002,43.324 r90 bottom
C58 ".designator" C0603 8.573,42.824 r90 bottom
C59 ".designator" C0603 6.795,42.824 r90 bottom
C60 ".designator" C0603 23.973,42.273 r180 bottom
C61 ".designator" C0603 73.293,41.693 r180 bottom
C62 ".designator" C0603 16.32,41.165 r180 bottom
C63 ".designator" C0603 5.805,41.036 r0 bottom
C64 ".designator" C0603 25.54,40.066 r0 bottom
C65 ".designator" C0603 97.913,39.533 r270 bottom
C66 ".designator" C0603 92.873,39.893 r180 bottom
C67 ".designator" C0603 36.093,39.333 r90 bottom
C68 ".designator" C0603 5.805,39.722 r0 bottom
C69 ".designator" C0603 33.213,39.493 r0 bottom
C70 ".designator" C0603 16.32,38.625 r180 bottom
C71 ".designator" C0603 5.805,38.387 r180 bottom
C72 ".designator" C0603 79.723,37.923 r0 bottom
C73 ".designator" C0603 34.147,37.02 r270 bottom
C74 ".designator" C0603 5.805,37.057 r180 bottom
C75 ".designator" CPOL_TAJ-A_1206_H180 20.014,35.524 r90 bottom
C76 ".designator" C0603 16.32,36.847 r0 bottom
C77 ".designator" C0603 16.32,35.577 r0 bottom
C78 ".designator" C0603 35.093,34.313 r0 bottom
C79 ".designator" C0603 88.233,33.373 r180 bottom
C80 ".designator" C0603 12.764,32.529 r90 bottom
C81 ".designator" C0603 11.494,32.529 r270 bottom
C82 ".designator" C0603 9.716,32.529 r270 bottom
C83 ".designator" C0603 31.442,31.716 r270 bottom
C84 ".designator" C0603 18.973,30.403 r180 bottom
C85 ".designator" C0603 76.133,29.413 r0 bottom
C86 ".designator" C0603 19.044,28.541 r90 bottom
C87 ".designator" CPOL_TAJ-A_1206_H180 76.183,26.993 r0 bottom
C88 ".designator" C0603 31.49,25.62 r90 bottom
C89 ".designator" C0603 18.972,24.961 r180 bottom
C90 ".designator" C0603 22.771,21.639 r270 bottom
C91 ".designator" C0603 69.163,21.203 r180 bottom
C92 ".designator" C0603 79.703,21.113 r180 bottom
C93 ".designator" C0603 79.703,19.763 r0 bottom
C94 ".designator" C0603 66.353,18.553 r90 bottom
C95 ".designator" C0603 65.073,18.553 r90 bottom
C96 ".designator" C0603 72.943,18.543 r90 bottom
C97 ".designator" C0603 71.633,18.543 r90 bottom
C98 ".designator" C0603 79.703,18.173 r0 bottom
C99 "C99" C0603 20.4,52.025 r180 bottom value=100nF
C100 "C100" C0603 25.45,52.025 r180 bottom value=100nF
C101 "C101" C0603 32.4,52.025 r180 bottom value=100nF
CN1 ".designator" CON_SAMTEC_SQT-110-01-F-D-RA__STMOD+ 80.463,58.407 r180 top locked
CN2 ".designator" CON_TOWNES_FPU330ZH-BT1D3-CA_P050 58.882,63.548 r180 top locked
CN3 ".designator" CON_SAMTEC_SSW-106-02-F-D-RA__PMOD 88.596,47.963 r90 top locked
CN4 ".designator" CON_SAMTEC_QSH-030-01-F-D-A 32.563,46.943 r0 top locked
CN5 ".designator" CON_988-JIUBABA_PHFS25-11-06-G0B115-T-1 97.413,18.513 r90 top locked
CN6 ".designator" CON_MICROSD_ATOM_MR01A-01211 28.893,0.013 r0 top locked
CN7 ".designator" CON_SAMTEC_SSM-104-L-DH 14.113,7.983 r180 top locked
CN8 ".designator" CON_TAG-C_TC2050-IDC-NL 72.203,3.738 r180 top locked
CN9 ".designator" CON_USBMICROAB_MOLEX_47590-0001_H3 58.763,-0.007 r0 top locked
CN10 ".designator" CON_SAMTEC_SSW-110-22-X-S-VS 55.916,58.161 r180 bottom locked
CN11 ".designator" CON_SAMTEC_SSW-108-22-X-S-VS 31.532,58.161 r180 bottom locked
CN12 ".designator" CON_PHONE-JACK-3P5_HY_PJ3028B 0.013,53.479 r0 bottom locked
CN13 ".designator" CON_USBMICROB_MOLEX_105017-0001_H2P90 100.013,31.013 r270 bottom locked
CN14 ".designator" CON_988-JIUBABA_PHFS25-11-04-G0B115-T-1 2.313,30.793 r270 bottom
CN15 ".designator" CON_988-JIUBABA_PHFS25-11-04-G0B115-T-1 88.273,26.763 r180 bottom locked
CN16 ".designator" CON_SAMTEC_SSW-108-22-X-S-VS 49.312,9.901 r0 bottom locked
CN17 ".designator" CON_SAMTEC_SSW-106-22-X-S-VS 28.992,9.901 r0 bottom locked
D1 ".designator" ESD_QFN2_1P6X1_P125 49.063,22.443 r270 top
D2 ".designator" ESD_QFN2_1P6X1_P125 62.223,7.057 r0 top
D3 ".designator" DIO_SOD323 16.433,28.463 r180 bottom
D4 ".designator" DIO_SOD323 71.803,13.403 r90 bottom
D5 ".designator" DIO_SOD323 69.833,13.403 r90 bottom
D6 ".designator" DIO_SOD323 67.873,13.403 r90 bottom
D7 ".designator" DIO_SOD323 91.443,13.283 r180 bottom
Designator2 "Designator2" CARTOUCHE_STM_BOTTOM -10.128,-38.128 r0 top
Designator3 "Designator3" CARTOUCHE_STM_TOP -10.203,-38.153 r0 top
H1 ".designator" PTH_350_700 4.513,62.513 r0 top locked
H2 ".designator" PTH_350_700 95.513,62.513 r0 top locked
H3 ".designator" PTH_350_700 4.513,4.513 r0 top
H4 ".designator" PTH_350_700 95.513,4.513 r0 top locked
JP1 ".designator" CON_988-JIUBABA_PHFS25-11-03-G0B115-T-1 74.597,51.027 r0 top locked
JP2 ".designator" CON_988-JIUBABA_PHFS25-11-02-G0B115-T-1 57.001,48.203 r0 top
JP3 ".designator" CON_988-JIUBABA_PHFS25-11-03-G0B115-T-1 71.063,24.013 r180 top
JP4 ".designator" CON_988-JIUBABA_PHFS25-12-10-G0B115-T-1 56.963,21.783 r0 top
JP5 ".designator" CON_988-JIUBABA_PHFS25-11-03-G0B115-T-1 62.063,15.403 r0 top
JP6 ".designator" CON_988-JIUBABA_PHFS25-11-02-G0B115-T-1 2.313,40.403 r270 bottom
JP7 ".designator" CON_988-JIUBABA_PHFS25-11-03-G0B115-T-1 2.313,19.803 r270 bottom
JP8 ".designator" CON_988-JIUBABA_PHFS25-11-02-G0B115-T-1 78.083,13.353 r180 bottom
JP9 ".designator" CON_988-JIUBABA_PHFS25-11-02-G0B115-T-1 2.313,11.713 r90 bottom
JP10 ".designator" CON_988-JIUBABA_PHFS25-11-03-G0B115-T-1 95.187,9.613 r180 bottom locked
L1 ".designator" L0603 32.373,57.093 r270 top
L2 ".designator" L0603 34.663,57.093 r270 top
L3 ".designator" L0603 64.568,48.548 r0 top
L4 ".designator" IND_MURATA_DFE201610C 8.373,21.763 r90 top
L5 ".designator" IND_MURATA_DFE201610C 8.363,16.673 r90 top
L6 ".designator" L0603 22.046,35.397 r270 bottom
LD1 ".designator" LED_0603_ORANGE_H0P4 44.803,61.453 r270 top
LD2 ".designator" LED_0603_GREEN_H0P8 46.913,61.453 r270 top
LD3 ".designator" LED_0603_GREEN_H0P8 42.693,61.453 r270 top
LD4 ".designator" LED_BI-GR_HSMF-A201-A00J1 89.553,30.213 r270 top
LD5 ".designator" LED_0603_RED_H0P4 73.793,15.273 r90 top
LD6 ".designator" LED_0603_GREEN_H0P8 53.063,3.513 r270 top
LD7 ".designator" LED_0603_RED_H0P4 64.147,7.107 r270 top
LD8 ".designator" LED_0603_GREEN_H0P8 7.813,11.703 r90 top
R1 ".designator" R0603 24.943,65.043 r0 top
R2 ".designator" R0603 42.693,64.463 r270 top
R3 ".designator" R0603 35.573,60.173 r0 top
R4 ".designator" R0603 56.123,58.993 r270 top
R5 ".designator" R0603 46.913,58.853 r90 top
R6 ".designator" R0603 41.003,56.023 r0 top
R7 ".designator" R0603 25.813,54.713 r270 top
R8 "R8" R0603 54.413,45.913 r180 top
R9 "R9" R0603 50.883,45.553 r0 top
R10 "R10" R0603 57.387,45.551 r0 top
R11 ".designator" R0603 48.463,45.173 r180 top
R12 "R12" R0603 54.413,44.513 r0 top value=100K
R13 ".designator" R0603 48.463,43.763 r180 top
R14 ".designator" R0603 68.374,42.685 r90 top
R15 ".designator" R0603 77.61,42.685 r270 top
R16 ".designator" R0603 79.134,42.685 r270 top
R17 ".designator" R0603 59.722,42.653 r0 top
R18 ".designator" R0603 88.774,37.876 r90 top
R19 ".designator" R0603 90.171,37.876 r90 top
R20 ".designator" R0603 87.403,34.543 r270 top
R21 ".designator" R0603 93.163,30.943 r180 top
R22 ".designator" R0603 85.963,29.463 r0 top
R23 ".designator" R0603 93.163,29.443 r180 top
R24 ".designator" R0603 82.623,24.193 r0 top
R25 ".designator" R0603 86.213,24.193 r0 top
R26 ".designator" R0603 82.623,22.853 r180 top
R27 ".designator" R0603 78.098,21.452 r0 top
R28 ".designator" R0603 92.393,20.143 r90 top
R29 ".designator" R0603 82.623,18.353 r180 top
R30 ".designator" R0603 92.393,17.793 r270 top
R31 ".designator" R0603 86.383,15.943 r90 top
R32 ".designator" R0603 92.873,15.923 r180 top
R33 ".designator" R0603 72.063,14.523 r180 top
R34 ".designator" R0603 87.553,13.403 r270 top
R35 ".designator" R0603 88.973,13.403 r90 top
R36 ".designator" R0603 90.373,13.403 r90 top
R37 ".designator" R0603 5.333,10.463 r180 top
R38 ".designator" R0603 63.663,9.753 r270 top
R39 ".designator" R0603 65.003,9.753 r270 top
R40 ".designator" R0603 75.073,9.803 r180 top
R41 ".designator" R0603 72.023,9.787 r0 top
R42 ".designator" R0603 53.183,7.283 r180 top
R43 ".designator" R0603 53.938,5.938 r0 top
R44 ".designator" R0603 17.993,64.333 r0 bottom
R45 ".designator" R0402 39.138,63.307 r90 bottom
R46 ".designator" R0402 42.803,62.293 r270 bottom
R47 ".designator" R0603 94.793,57.183 r0 bottom
R48 ".designator" R0603 97.863,54.233 r90 bottom
R49 ".designator" R0603 42.293,52.61 r270 bottom
R50 ".designator" R0603 30.55,53.85 r270 bottom
R51 ".designator" R0603 97.888,51.703 r270 bottom
R52 ".designator" R0603 96.533,51.703 r270 bottom
R53 ".designator" R0603 95.173,51.703 r270 bottom
R54 ".designator" R0603 77.453,47.553 r180 bottom
R55 ".designator" R0805 38.897,46.613 r0 bottom
R56 ".designator" R0603 77.453,46.203 r180 bottom
R57 ".designator" R0603 8.573,45.245 r90 bottom
R58 ".designator" R0603 6.795,45.245 r90 bottom
R59 ".designator" R0603 17.082,43.324 r90 bottom
R60 ".designator" R0603 34.323,41.613 r90 bottom
R61 ".designator" R0603 75.833,41.703 r180 bottom
R62 ".designator" R0805 39.243,40.652 r0 bottom
R63 ".designator" R0603 96.613,39.533 r90 bottom
R64 ".designator" R0603 16.32,39.895 r180 bottom
R65 ".designator" R0603 30.874,39.508 r0 bottom
R66 ".designator" R0603 28.483,39.508 r180 bottom
R67 ".designator" R0603 89.594,38.827 r90 bottom
R68 ".designator" R0603 87.674,39.297 r0 bottom
R69 ".designator" R0603 95.283,38.793 r90 bottom
R70 ".designator" R0603 25.54,38.669 r180 bottom
R71 ".designator" R0603 93.943,37.693 r90 bottom
R72 ".designator" R0603 92.603,37.693 r90 bottom
R73 ".designator" R0603 91.253,37.693 r90 bottom
R74 ".designator" R0603 43.803,37.353 r270 bottom
R75 ".designator" R0603 36.803,37.02 r270 bottom
R76 ".designator" R0603 35.463,37.02 r270 bottom
R77 ".designator" R0603 25.54,37.272 r0 bottom
R78 ".designator" R0603 89.414,36.917 r0 bottom
R79 ".designator" R0603 25.54,35.906 r0 bottom
R80 ".designator" R0603 5.805,35.229 r0 bottom
R81 ".designator" R0805 39.523,33.893 r0 bottom
R82 ".designator" R0603 17.423,32.529 r90 bottom
R83 ".designator" R0603 15.423,32.529 r90 bottom
R84 ".designator" R0603 43.803,31.023 r90 bottom
R85 ".designator" R0805 38.523,30.673 r270 bottom
R86 ".designator" R0603 93.738,28.963 r0 bottom
R87 ".designator" R0603 18.973,26.323 r0 bottom
R88 ".designator" R0603 80.163,25.333 r90 bottom
R89 ".designator" R0603 43.803,25.223 r90 bottom
R90 ".designator" R0603 37.693,25.223 r270 bottom
R91 ".designator" R0603 80.163,23.033 r270 bottom
R92 ".designator" R0603 78.813,23.033 r90 bottom
R93 ".designator" R0603 77.463,23.033 r90 bottom
R94 ".designator" R0603 92.193,23.023 r90 bottom
R95 ".designator" R0603 25.438,21.639 r270 bottom
R96 ".designator" R0603 24.096,21.639 r270 bottom
R97 ".designator" R0603 21.113,21.639 r90 bottom
R98 ".designator" R0603 93.853,18.443 r180 bottom
R99 ".designator" R0603 14.143,16.063 r270 bottom
R100 ".designator" R0603 11.613,16.063 r270 bottom
R101 ".designator" R0603 80.083,16.173 r0 bottom
R102 ".designator" R0603 77.783,16.173 r0 bottom
R103 ".designator" R0603 88.993,13.073 r90 bottom
R104 ".designator" R0603 87.643,13.073 r270 bottom
R105 ".designator" R0603 86.273,13.073 r90 bottom
R106 ".designator" R0603 83.423,13.073 r270 bottom
R107 ".designator" R0603 13.073,12.323 r270 bottom
R108 ".designator" R0603 10.513,12.323 r270 bottom
R109 ".designator" R0603 60.963,9.893 r270 bottom
R110 ".designator" R0603 75.773,8.223 r0 bottom
R111 ".designator" R0603 73.303,8.223 r0 bottom
R112 ".designator" R0603 13.043,6.943 r90 bottom
R113 ".designator" R0603 50.688,5.788 r180 bottom
R114 ".designator" R0603 49.813,3.913 r90 bottom
R115 ".designator" R0603 65.033,3.653 r270 bottom
R116 "R116" R0603 23.475,53.85 r270 bottom value=56K
R117 "R117" R0603 17.775,54.825 r0 bottom value=6.8K
R118 "R118" R0603 25.45,53.375 r180 bottom value=0
R119 "R119" R0603 32.4,53.375 r180 bottom value=0
R120 "R120" R0603 20.4,53.375 r180 bottom value=0
SB1 ".designator" SOLDER-BRIDGE_R0603-0R 22.493,61.433 r90 top
SB2 ".designator" SOLDER-BRIDGE_R0603-0R 38.453,56.683 r90 top
SB3 ".designator" SOLDER-BRIDGE_R0603-0R 50.186,50.594 r270 top
SB4 ".designator" SOLDER-BRIDGE_R0603-0R 50.185,47.815 r90 top
SB5 "SB5" SOLDER-BRIDGE_R0603-0R 48.95,40.875 r90 top
SB6 ".designator" SOLDER-BRIDGE_R0603-0R 29.96,40.723 r270 top
SB7 ".designator" SOLDER-BRIDGE_R0603-0R 31.903,40.723 r270 top
SB8 ".designator" SOLDER-BRIDGE_R0603-0R 33.454,40.723 r270 top
SB9 "SB9" SOLDER-BRIDGE_R0603-0R 35.072,40.723 r270 top
SB10 "SB10" SOLDER-BRIDGE_R0603-0R 36.689,40.723 r270 top
SB11 "SB11" SOLDER-BRIDGE_R0603-0R 38.306,40.723 r270 top
SB12 "SB12" SOLDER-BRIDGE_R0603-0R 39.923,40.723 r270 top
SB13 ".designator" SOLDER-BRIDGE_R0603-0R 28.413,40.703 r270 top
SB14 ".designator" SOLDER-BRIDGE_R0603-0R 86.273,22.303 r180 top
SB15 ".designator" SOLDER-BRIDGE_R0603-0R 72.233,11.743 r180 top
SB16 ".designator" SOLDER-BRIDGE_R0603-0R 68.733,63.733 r90 bottom
SB17 ".designator" SOLDER-BRIDGE_R0603-0R 67.093,63.733 r90 bottom
SB18 ".designator" SOLDER-BRIDGE_R0603-0R 63.593,63.733 r90 bottom
SB19 ".designator" SOLDER-BRIDGE_R0603-0R 61.963,63.733 r90 bottom
SB20 ".designator" SOLDER-BRIDGE_R0603-0R 50.033,63.733 r90 bottom
SB21 ".designator" SOLDER-BRIDGE_R0603-0R 48.403,63.733 r90 bottom
SB22 ".designator" SOLDER-BRIDGE_R0603-0R 40.323,63.733 r90 bottom
SB23 ".designator" SOLDER-BRIDGE_R0603-0R 97.433,57.183 r180 bottom
SB24 ".designator" SOLDER-BRIDGE_R0603-0R 96.033,54.633 r270 bottom
SB25 ".designator" SOLDER-BRIDGE_R0603-0R 94.453,54.633 r90 bottom
SB26 ".designator" SOLDER-BRIDGE_R0603-0R 92.873,54.633 r90 bottom
SB27 ".designator" SOLDER-BRIDGE_R0603-0R 60.103,54.323 r180 bottom
SB28 ".designator" SOLDER-BRIDGE_R0603-0R 84.788,51.263 r90 bottom
SB29 ".designator" SOLDER-BRIDGE_R0603-0R 10.224,43.324 r270 bottom locked
SB30 ".designator" SOLDER-BRIDGE_R0603-0R 14.034,32.529 r90 bottom
SB31 ".designator" SOLDER-BRIDGE_R0603-0R 27.823,21.593 r180 bottom
SB32 ".designator" SOLDER-BRIDGE_R0603-0R 25.933,14.363 r270 bottom
SB33 ".designator" SOLDER-BRIDGE_R0603-0R 24.413,14.363 r270 bottom
SB34 ".designator" SOLDER-BRIDGE_R0603-0R 22.247,14.363 r270 bottom locked
SB35 ".designator" SOLDER-BRIDGE_R0603-0R 20.723,14.363 r270 bottom
SB36 ".designator" SOLDER-BRIDGE_R0603-0R 84.863,12.863 r90 bottom
SB37 ".designator" SOLDER-BRIDGE_R0603-0R 18.113,7.133 r90 bottom
SB38 "SB38" SOLDER-BRIDGE_R0603-0R 48.425,37.05 r90 top
SB39 "SB39" SOLDER-BRIDGE_R0603-0R 36.425,36.375 r180 top
SW1 "SW1" SWI_GRAYHILL-INC_EDG-501S_DI 84.923,6.083 r0 bottom
T1 ".designator" MOS_SOT23 41.013,58.663 r0 top
T2 ".designator" MOS_SOT23-6L 41.363,49.423 r0 bottom
T3 ".designator" MOS_SOT23-6L 36.013,49.423 r0 bottom
T4 ".designator" MOS_SOT23-6L 31.013,49.423 r0 bottom
T5 ".designator" MOS_SOT23-6L 26.013,49.423 r0 bottom
T6 ".designator" MOS_SOT23-6L 21.013,49.423 r0 bottom
T7 ".designator" MOS_SOT23-6L 41.363,37.396 r0 bottom
T8 ".designator" MOS_SOT23-6L 41.373,30.986 r0 bottom
T9 ".designator" MOS_SOT23-6L 35.263,30.986 r0 bottom
T10 ".designator" MOS_SOT23-6L 41.373,25.226 r0 bottom
T11 ".designator" MOS_SOT23-6L 35.263,25.226 r0 bottom
T12 ".designator" NPN_SOT23 93.883,15.823 r0 bottom
T13 ".designator" NPN_SOT23 52.263,3.138 r0 bottom
U1 ".designator" MIC_HCLGA_3X4X1_4LD 12.013,64.013 r90 top
U2 ".designator" MIC_HCLGA_3X4X1_4LD 33.013,64.013 r90 top
U3 ".designator" ESD_SOT323-5L 24.973,62.743 r180 top
U4 ".designator" ESD_SOT23 10.283,57.043 r0 top
U5 ".designator" ICC_MINI-BGA48_6X8_P075 54.194,39.383 r0 top locked
U6 ".designator" ICC_VFBGA54_6X8_P075 54.194,39.008 r0 top locked
U7 ".designator" ICC_UFBGA169_7X7_P050 73.117,36.208 r270 top locked
U8 ".designator" ICC_VSSOP8_DCU_R-PDSO-G8_2X2P30_P050 89.483,34.503 r180 top
U9 ".designator" ICC_DSBGA8_0P88X1P57_P040 6.173,21.263 r180 top
U10 ".designator" ICC_VSSOP8_DCU_R-PDSO-G8_2X2P30_P050 86.293,19.263 r180 top
U11 ".designator" ICC_SO8_5X4_P127_DI-DFN8 77.943,17.933 r90 top
U12 ".designator" ESD_SOT323-5L 94.513,19.103 r0 top
U13 ".designator" ESD_UQFN16L-EPAD_3P5X1P2_P040 27.313,17.747 r180 top locked
U14 ".designator" ICC_DSBGA8_0P88X1P57_P040 6.153,16.183 r180 top
U15 ".designator" REG_SOT223-TAB 53.983,12.253 r180 top
U16 ".designator" MOS_SOT23-5L 68.9,10.726 r270 top
U17 ".designator" ESD_SOT323-5L 41.853,10.243 r135 top
U18 ".designator" ESD_SOT23-6L 59.077,7.006 r270 top
U19 ".designator" MIC_STM_MP23DB01MMTR#1 36.263,64.013 r180 bottom
U20 ".designator" MIC_STM_MP23DB01MMTR#2 15.263,64.013 r180 bottom
U21 ".designator" ICC_UFQFN16-EPAD_2P6X1P8_P040 43.413,64.313 r180 bottom
U22 ".designator" ESD_SOT23-6L 11.323,48.463 r90 bottom
U23 ".designator" ICC_BGA24_5X5-BALL-ARRAY_6X8_P1 95.283,45.583 r180 bottom locked
U24 ".designator" ICC_BGA24_5X5-BALL-ARRAY_6X8_P1 95.283,45.583 r180 bottom
U25 ".designator" ICC_MINISO8_3X3_P065 30.493,41.971 r270 bottom
U26 ".designator" ICC_QFN32-EPAD_5X5_P050 11.118,37.863 r90 bottom locked
U27 ".designator" ICC_MINISO8_3X3_P065 30.493,37.018 r270 bottom
U28 ".designator" ESD_SOT23-6L 92.953,31.353 r270 bottom locked
U29 ".designator" ICC_LQFP48_7X7_P050 25.521,28.033 r90 bottom locked
U30 ".designator" ICC_LQFP48_7X7_P050 86.233,19.443 r90 bottom locked
U31 ".designator" MOS_SOT23-5L 69.083,18.803 r90 bottom
U32 ".designator" ESD_SOT323-5L 72.213,3.363 r180 bottom locked value=ESDALC6V1W5
U33 "U33" ICC_DFN8-EPAD_3X3_P065_DI-SO8 77.943,17.933 r90 top
X1 ".designator" CRY_NX3215SA_2P 73.423,45.843 r180 top
X2 ".designator" CRY_NX3225HA_4P 81.963,46.933 r180 bottom
X3 ".designator" CRY_NX3225GD_2P 77.043,18.973 r270 bottom

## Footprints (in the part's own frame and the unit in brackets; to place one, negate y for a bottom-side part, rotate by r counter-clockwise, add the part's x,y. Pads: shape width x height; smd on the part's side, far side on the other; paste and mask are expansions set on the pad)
C0402 [mm]
  rect 0.51x0.56 smd mask+0.05: 1(-0.45,0) 2(0.45,0)
  silkscreen extent -0.72,-0.35 0.72,0.35, body extent -0.5,-0.3 0.5,0.3, height 0.4
C0603 [mm]
  rect 0.64x0.89 smd mask+0.05: 1(-0.7,0) 2(0.7,0)
  silkscreen extent -1.05,-0.55 1.02,0.55, body extent -0.9,-0.5 0.9,0.5, height 1.4
CARTOUCHE_STM_BOTTOM [mm]
CARTOUCHE_STM_TOP [mm]
CON_988-JIUBABA_PHFS25-11-02-G0B115-T-1 [mm]
  rect 1.6x1.6 hole 1 mask+0.05: 1(1.27,0)
  round 1.6 hole 1 mask+0.05: 2(-1.27,0)
  silkscreen extent -2.71,-1.33 2.71,1.33, body extent -2.71,-1.33 2.71,1.33, height 8.85
CON_988-JIUBABA_PHFS25-11-03-G0B115-T-1 [mm]
  rect 1.6x1.6 hole 1 mask+0.05: 1(2.54,0)
  round 1.6 hole 1 mask+0.05: 2(0,0) 3(-2.54,0)
  silkscreen extent -3.98,-1.33 3.98,1.33, body extent -3.98,-1.33 3.98,1.33, height 8.85
CON_988-JIUBABA_PHFS25-11-04-G0B115-T-1 [mm]
  rect 1.6x1.6 hole 1 mask+0.05: 1(3.81,0)
  round 1.6 hole 1 mask+0.05: 2(1.27,0) 3(-1.27,0) 4(-3.81,0)
  silkscreen extent -5.25,-1.33 5.25,1.33, body extent -5.25,-1.33 5.25,1.33, height 8.85
CON_988-JIUBABA_PHFS25-11-06-G0B115-T-1 [mm]
  rect 1.6x1.6 hole 1 mask+0.05: 1(6.35,0)
  round 1.6 hole 1 mask+0.05: 2(3.81,0) 3(1.27,0) 4(-1.27,0) 5(-3.81,0) 6(-6.35,0)
  silkscreen extent -7.79,-1.33 7.79,1.33, body extent -7.79,-1.33 7.79,1.33, height 8.85
CON_988-JIUBABA_PHFS25-12-10-G0B115-T-1 [mm]
  rect 1.7x1.7 hole 1.1 mask+0.05: 1(-5.08,-1.27)
  round 1.7 hole 1.1 mask+0.05: 2(-5.08,1.27) 3(-2.54,-1.27) 4(-2.54,1.27) 5(0,-1.27) 6(0,1.27) 7(2.54,-1.27) 8(2.54,1.27) 9(5.08,-1.27) 10(5.08,1.27)
  silkscreen extent -6.6,-2.6 6.6,2.6, body extent -6.6,-2.6 6.6,2.6, height 8.85
CON_MICROSD_ATOM_MR01A-01211 [mm]
  rect 0.7x1.6 smd paste+0 mask+0.05: 1(2.25,14.5) 2(1.15,14.5) 3(0.05,14.5) 4(-1.05,14.5) 5(-2.15,14.5) 6(-3.25,14.5) 7(-4.35,14.5) 8(-5.45,14.5) 9(-6.55,14.5)
  rect 1.2x1.6 smd paste+0 mask+0.05: 10(-7.75,13.9)
  rect 1.2x2.2 smd paste+0 mask+0.05: 11(-7.75,4.4) 12(7.75,4.4)
  rect 1.6x1.4 smd paste+0 mask+0.05: 13(6.85,14)
  round 0.5 hole 1 unplated mask+0.05: NPTH1(-4.95,4) NPTH2(3.05,4)
  Top Layer pour cut-out: -8.35,8.1 -8.35,12.9 -6.9,12.9 -6.9,8.1
  Top Layer pour cut-out: -6.1,10.1 2.9,10.1 2.9,8.1 -6.1,8.1
  Top Layer keep-out region: -8.35,8.1 -8.35,12.9 -6.9,12.9 -6.9,8.1
  Top Layer keep-out region: -6.1,10.1 2.9,10.1 2.9,8.1 -6.1,8.1
  silkscreen extent -7.35,-5.3 7.35,14.5, body extent -8.05,0 8.05,15, height 1.9
CON_PHONE-JACK-3P5_HY_PJ3028B [mm]
  rect 1.5x2.5 smd mask+0.05: 2(1.25,-3.45) 7(2.85,3.45)
  rect 2x2.5 smd mask+0.05: 3(4,-3.45) 4(5.8,3.45) 6(13.2,-3.45)
  rect 2.5x2 smd mask+0.05: 5(17.25,0.75)
  round 0.5 hole 2 unplated mask+0.1: MT1(5,0) MT2(12,0)
  Multi-Layer keep-out circle w0.01: c12,0 r1.25
  Multi-Layer keep-out circle w0.01: c5,0 r1.25
  silkscreen extent -0.9,-3.7 16,3, body extent -0.9,-3 16,3, height 5
CON_SAMTEC_QSH-030-01-F-D-A [mm]
  rect 0.3x2.27 smd mask+0.05: 1(7.25,2.87) 2(7.25,-2.87) 3(6.75,2.87) 4(6.75,-2.87) 5(6.25,2.87) 6(6.25,-2.87) 7(5.75,2.87) 8(5.75,-2.87) 9(5.25,2.87) 10(5.25,-2.87) 11(4.75,2.87) 12(4.75,-2.87) 13(4.25,2.87) 14(4.25,-2.87) 15(3.75,2.87) 16(3.75,-2.87) 17(3.25,2.87) 18(3.25,-2.87) 19(2.75,2.87) 20(2.75,-2.87) 21(2.25,2.87) 22(2.25,-2.87) 23(1.75,2.87) 24(1.75,-2.87) 25(1.25,2.87) 26(1.25,-2.87) 27(0.75,2.87) 28(0.75,-2.87) 29(0.25,2.87) 30(0.25,-2.87) 31(-0.25,2.87) 32(-0.25,-2.87) 33(-0.75,2.87) 34(-0.75,-2.87) 35(-1.25,2.87) 36(-1.25,-2.87) 37(-1.75,2.87) 38(-1.75,-2.87) 39(-2.25,2.87) 40(-2.25,-2.87) 41(-2.75,2.87) 42(-2.75,-2.87) 43(-3.25,2.87) 44(-3.25,-2.87) 45(-3.75,2.87) 46(-3.75,-2.87) 47(-4.25,2.87) 48(-4.25,-2.87) 49(-4.75,2.87) 50(-4.75,-2.87) 51(-5.25,2.87) 52(-5.25,-2.87) 53(-5.75,2.87) 54(-5.75,-2.87) 55(-6.25,2.87) 56(-6.25,-2.87) 57(-6.75,2.87) 58(-6.75,-2.87) 59(-7.25,2.87) 60(-7.25,-2.87)
  rect 2.54x0.43 smd mask+0.05: 61(8.063,0) 64(-8.063,0)
  rect 4.7x0.43 smd mask+0.05: 62(3.175,0) 63(-3.175,0)
  round 0.5 hole 1.05 unplated mask+0.1: 65(-10.065,-2.67) 66(10.065,-2.67)
  Multi-Layer keep-out circle w0.01: c10.065,-2.67 r0.801
  Multi-Layer keep-out circle w0.01: c-10.065,-2.67 r0.801
  silkscreen extent -10.8,-3.7 10.8,3.7, body extent -10.8,-3.75 10.8,3.75, height 3.26
CON_SAMTEC_SQT-110-01-F-D-RA__STMOD+ [mm] "SQT-110-01-F-D-RA (connecteur SAMTEC pour interface STMod+ femelle coté Host) Pinning adapté non conforme SAMTEC."
  rect 1.63x1.63 hole 0.9 mask+0.05: 1(9,1)
  round 1.63 hole 0.9 mask+0.05: 2(7,1) 3(5,1) 4(3,1) 5(1,1) 6(-1,1) 7(-3,1) 8(-5,1) 9(-7,1) 10(-9,1) 11(9,-1) 12(7,-1) 13(5,-1) 14(3,-1) 15(1,-1) 16(-1,-1) 17(-3,-1) 18(-5,-1) 19(-7,-1) 20(-9,-1)
  silkscreen extent -10.15,-8.62 10.15,0.07, body extent -10.15,-8.65 10.15,1.22, height 4
CON_SAMTEC_SSM-104-L-DH [mm]
  rect 1.2x3.4 smd mask+0.05: 1(3.81,-5) 2(3.81,5) 3(1.27,-5) 4(1.27,5) 5(-1.27,-5) 6(-1.27,5) 7(-3.81,-5) 8(-3.81,5)
  silkscreen extent -5.08,-4.06 5.08,4.06, body extent -5.08,-5.46 5.11,5.46, height 5.92
CON_SAMTEC_SSW-106-02-F-D-RA__PMOD [mm] "SSW-106-02-F-D-RA (connecteur SAMTEC pour interface PMOD femelle coté Host) Pinning adapté non conforme SAMTEC."
  rect 1.9x1.9 hole 1.1 mask+0.05: 1(6.35,1.27)
  round 1.9 hole 1.1 mask+0.05: 2(3.81,1.27) 3(1.27,1.27) 4(-1.27,1.27) 5(-3.81,1.27) 6(-6.35,1.27) 7(6.35,-1.27) 8(3.81,-1.27) 9(1.27,-1.27) 10(-1.27,-1.27) 11(-3.81,-1.27) 12(-6.35,-1.27)
  silkscreen extent -7.88,-11.3 7.88,0.23, body extent -7.87,-11.31 7.87,1.47, height 5.21
CON_SAMTEC_SSW-106-22-X-S-VS [mil]
  rect 40x95 smd mask+1.97: 1(250,67.5) 2(150,-67.5) 3(50,67.5) 4(-50,-67.5) 5(-150,67.5) 6(-250,-67.5)
  silkscreen extent -310,-48 310,48, body extent -310,-101 310,102, height 385
CON_SAMTEC_SSW-108-22-X-S-VS [mil]
  rect 40x95 smd mask+1.97: 1(350,67.5) 2(250,-67.5) 3(150,67.5) 4(50,-67.5) 5(-50,67.5) 6(-150,-67.5) 7(-250,67.48) 8(-350,-67.48)
  silkscreen extent -410,-48 410,48, body extent -410,-101 410,102, height 385
CON_SAMTEC_SSW-110-22-X-S-VS [mil]
  rect 40x95 smd mask+1.97: 1(450,67.5) 2(350,-67.5) 3(250,67.5) 4(150,-67.5) 5(50,67.5) 6(-50,-67.5) 7(-150,67.48) 8(-250,-67.48) 9(-350,67.48) 10(-450,-67.48)
  silkscreen extent -510,-48 510,48, body extent -510,-101 510,102, height 385
CON_TAG-C_TC2050-IDC-NL [mm]
  round 0.9 smd paste+0 mask+0.05: 1(-2.54,-0.635) 2(-1.27,-0.635) 3(0,-0.635) 4(1.27,-0.635) 5(2.54,-0.635) 6(2.54,0.635) 7(1.27,0.635) 8(0,0.635) 9(-1.27,0.635) 10(-2.54,0.635)
  round 0 hole 1.1 unplated mask+0.05: 11(-3.81,0) 12(3.81,-1.015) 13(3.81,1.015)
  Multi-Layer keep-out circle w0.01: c3.81,-1.015 r0.75
  Multi-Layer keep-out circle w0.01: c3.81,1.015 r0.75
  Multi-Layer keep-out circle w0.01: c-3.81,0 r0.75
  silkscreen extent -6.22,-3.4 6.22,3.33, body extent -6.28,-3.46 6.28,3.39, height 13
CON_TOWNES_FPU330ZH-BT1D3-CA_P050 [mm]
  rect 0.3x1.25 smd mask+0.05: 1(-7.25,2.575) 2(-6.75,2.575) 3(-6.25,2.575) 4(-5.75,2.575) 5(-5.25,2.575) 6(-4.75,2.575) 7(-4.25,2.575) 8(-3.75,2.575) 9(-3.25,2.575) 10(-2.75,2.575) 11(-2.25,2.575) 12(-1.75,2.575) 13(-1.25,2.575) 14(-0.75,2.575) 15(-0.25,2.575) 16(0.25,2.575) 17(0.75,2.575) 18(1.25,2.575) 19(1.75,2.575) 20(2.25,2.575) 21(2.75,2.575) 22(3.25,2.575) 23(3.75,2.575) 24(4.25,2.575) 25(4.75,2.575) 26(5.25,2.575) 27(5.75,2.575) 28(6.25,2.575) 29(6.75,2.575) 30(7.25,2.575)
  rect 2x2.5 smd mask+0.05: 31(-8.94,0) 32(8.94,0)
  silkscreen extent -9.7,-2.9 9.7,2.3, body extent -10.25,-4.25 10.25,3, height 2.05
CON_USBMICROAB_MOLEX_47590-0001_H3 [mm]
  rect 0.4x1.35 smd mask+0.05: 1(1.3,4.125) 2(0.65,4.125) 3(0,4.125) 4(-0.65,4.125) 5(-1.3,4.125)
  oval 1.05x1.25 hole 0.65 slot 0.85 at 90 deg mask+0.05: 6(-2.225,4.45) 7(2.225,4.45)
  rrect50% 1.375x1.9 hole 0.6 slot 1.3 at 90 deg copper offset 0.188,0 mask+0.05: 8(-4.175,1.45)
  rrect50% 1.375x1.9 hole 0.6 slot 1.3 at 90 deg copper offset -0.188,0 mask+0.05: 9(4.175,1.45)
  rect 2.9x1.9 smd mask+0.05: 10(0,1.45)
  oval 0.85x2.425 hole 0.85 slot 2.425 at 90 deg unplated mask+0.1: 11(-2.375,0.8) 12(2.375,0.8)
  silkscreen extent -4.1,-1.3 4.1,4.3, body extent -4.33,-1.36 4.32,4.6, height 3
CON_USBMICROB_MOLEX_105017-0001_H2P90 [mm]
  rect 0.4x1.35 smd mask+0.05: 1(-1.3,4.15) 2(-0.65,4.15) 3(0,4.15) 4(0.65,4.15) 5(1.3,4.15)
  round 1.5 hole 0.9 mask+0.05: 6(-2.5,4.15) 7(2.5,4.15)
  oval 1.2x1.9 hole 0.6 slot 1.3 at 90 deg mask+0.05: 8(3.5,1.45) 9(-3.5,1.45)
  rect 1.5x1.9 smd mask+0.05: 10(-1,1.45) 11(1,1.45)
  Top Layer region: 2.3,2.4 3.5,2.4 3.5,0.5 2.3,0.5 2.3,2.4
  Top Layer region: -3.5,2.4 -2.3,2.4 -2.3,0.5 -3.5,0.5 -3.5,2.4
  silkscreen extent -4,-0.7 4,4.6, body extent -4.1,-1.15 4.1,4.66, height 2.9
CPOL_TAJ-A_1206_H180 [mm]
  rect 1.45x1.6 smd mask+0.05: 1(-1.175,0) 2(1.175,0)
  silkscreen extent -2.15,-1.05 1.7,1.05, body extent -1.7,-0.9 1.7,0.9, height 1.8
CPOL_TAJ-B_1210_H210 [mm]
  rect 1.35x2.8 smd mask+0.05: 1(-1.375,0) 2(1.375,0)
  silkscreen extent -2.33,-1.68 1.85,1.68, body extent -1.85,-1.5 1.85,1.5, height 2.11
CRY_NX3215SA_2P [mm]
  rect 1x1.8 smd mask+0.05: 1(-1.25,0) 2(1.25,0)
  silkscreen extent -0.63,-0.8 0.63,0.8, body extent -1.65,-0.8 1.65,0.8, height 0.9
CRY_NX3225GD_2P [mm]
  rect 1.5x2.7 smd mask+0.05: 1(-0.95,0) 2(0.95,0)
  silkscreen extent -0.1,-1.3 0.1,1.3, body extent -1.65,-1.3 1.65,1.3, height 1
CRY_NX3225HA_4P [mm]
  rect 1.4x1.2 smd mask+0.05: 1(-1.1,-0.8) 2(1.1,-0.8) 3(1.1,0.8) 4(-1.1,0.8)
  silkscreen extent -1.9,-1.5 1.65,1.3, body extent -1.66,-1.31 1.66,1.31, height 0.91
DIO_SOD323 [mm]
  rect 1.06x0.54 smd mask+0.05: 1(-1.07,0) 2(1.07,0)
  silkscreen extent -0.9,-0.72 0.9,0.72, body extent -1.3,-0.78 1.3,0.78, height 1.17
ESD_QFN2_1P6X1_P125 [mm]
  rect 0.55x0.8 smd mask+0.05: 1(-0.625,0) 2(0.625,0)
  silkscreen extent -1,-0.55 0.85,0.55, body extent -0.85,-0.55 0.85,0.55, height 0.61
ESD_SOT23 [mm]
  rect 1x1.4 smd mask+0.05: 1(-0.95,-1.1) 2(0.95,-1.1) 3(0,1.1)
  silkscreen extent -1.63,-0.82 1.63,0.82, body extent -1.56,-1.5 1.56,1.5, height 1.4
ESD_SOT23-6L [mm]
  rect 0.6x1.2 smd mask+0.05: 1(-0.95,-1.15) 2(0,-1.15) 3(0.95,-1.15) 4(0.95,1.15) 5(0,1.15) 6(-0.95,1.15)
  silkscreen extent -1.53,-0.87 1.53,0.87, body extent -1.52,-1.5 1.52,1.5, height 1.45
ESD_SOT323-5L [mm]
  rect 0.4x1.2 smd mask+0.05: 1(-0.65,-0.85) 2(0,-0.85) 3(0.65,-0.85) 4(0.65,0.85) 5(-0.65,0.85)
  silkscreen extent -1.22,-1.11 1.22,0.77, body extent -1.15,-1.05 1.15,1.05, height 1.1
ESD_UQFN16L-EPAD_3P5X1P2_P040 [mm]
  rect 0.2x0.45 smd mask+0.05: 1(-1.4,-0.575) 2(-1,-0.575) 3(-0.6,-0.575) 4(-0.2,-0.575) 5(0.2,-0.575) 6(0.6,-0.575) 7(1,-0.575) 8(1.4,-0.575) 9(1.4,0.575) 10(1,0.575) 11(0.6,0.575) 12(0.2,0.575) 13(-0.2,0.575) 14(-0.6,0.575) 15(-1,0.575) 16(-1.4,0.575)
  rect 2.8x0.3 smd mask+0.05: EP(0,0)
  silkscreen extent -1.78,-0.63 1.78,0.63, body extent -1.78,-0.63 1.78,0.63, height 0.56
ICC_BGA24_5X5-BALL-ARRAY_6X8_P1 [mm]
  round 0.45 smd mask+0.05: A2(-1,2) A3(0,2) A4(1,2) A5(2,2) B1(-2,1) B2(-1,1) B3(0,1) B4(1,1) B5(2,1) C1(-2,0) C2(-1,0) C3(0,0) C4(1,0) C5(2,0) D1(-2,-1) D2(-1,-1) D3(0,-1) D4(1,-1) D5(2,-1) E1(-2,-2) E2(-1,-2) E3(0,-2) E4(1,-2) E5(2,-2)
  silkscreen extent -3.05,-4.05 3.05,4.05, body extent -3.05,-4.05 3.05,4.05, height 1.2
ICC_DFN8-EPAD_3X3_P065_DI-SO8 [mm] "SPT ON MECH-4"
  rect 0.35x0.35 smd paste-10 mask+0.05: 1(-0.975,-1.35) 2(-0.325,-1.35) 3(0.325,-1.35) 4(0.975,-1.35) 5(0.975,1.35) 6(0.325,1.35) 7(-0.325,1.35) 8(-0.975,1.35)
  rect 2.5x1.9 smd paste-10 mask+0.05: 9(0,0)
  silkscreen extent -1.53,-1.53 1.53,1.53, body extent -1.53,-1.53 1.53,1.53, height 0.9
ICC_DSBGA8_0P88X1P57_P040 [mm]
  round 0.2 smd mask+0.05: A1(-0.2,0.6) A2(0.2,0.6) B1(-0.2,0.2) B2(0.2,0.2) C1(-0.2,-0.2) C2(0.2,-0.2) D1(-0.2,-0.6) D2(0.2,-0.6)
  silkscreen extent -0.53,-0.82 0.45,0.9, body extent -0.45,-0.8 0.45,0.8, height 0.51
ICC_LQFP48_7X7_P050 [mm]
  rect 0.3x1.2 smd mask+0.05: 1(-2.75,-4.25) 2(-2.25,-4.25) 3(-1.75,-4.25) 4(-1.25,-4.25) 5(-0.75,-4.25) 6(-0.25,-4.25) 7(0.25,-4.25) 8(0.75,-4.25) 9(1.25,-4.25) 10(1.75,-4.25) 11(2.25,-4.25) 12(2.75,-4.25) 25(2.75,4.25) 26(2.25,4.25) 27(1.75,4.25) 28(1.25,4.25) 29(0.75,4.25) 30(0.25,4.25) 31(-0.25,4.25) 32(-0.75,4.25) 33(-1.25,4.25) 34(-1.75,4.25) 35(-2.25,4.25) 36(-2.75,4.25)
  rect 1.2x0.3 smd mask+0.05: 13(4.25,-2.75) 14(4.25,-2.25) 15(4.25,-1.75) 16(4.25,-1.25) 17(4.25,-0.75) 18(4.25,-0.25) 19(4.25,0.25) 20(4.25,0.75) 21(4.25,1.25) 22(4.25,1.75) 23(4.25,2.25) 24(4.25,2.75) 37(-4.25,2.75) 38(-4.25,2.25) 39(-4.25,1.75) 40(-4.25,1.25) 41(-4.25,0.75) 42(-4.25,0.25) 43(-4.25,-0.25) 44(-4.25,-0.75) 45(-4.25,-1.25) 46(-4.25,-1.75) 47(-4.25,-2.25) 48(-4.25,-2.75)
  silkscreen extent -3.52,-3.52 3.52,3.52, body extent -4.5,-4.5 4.5,4.5, height 1.6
